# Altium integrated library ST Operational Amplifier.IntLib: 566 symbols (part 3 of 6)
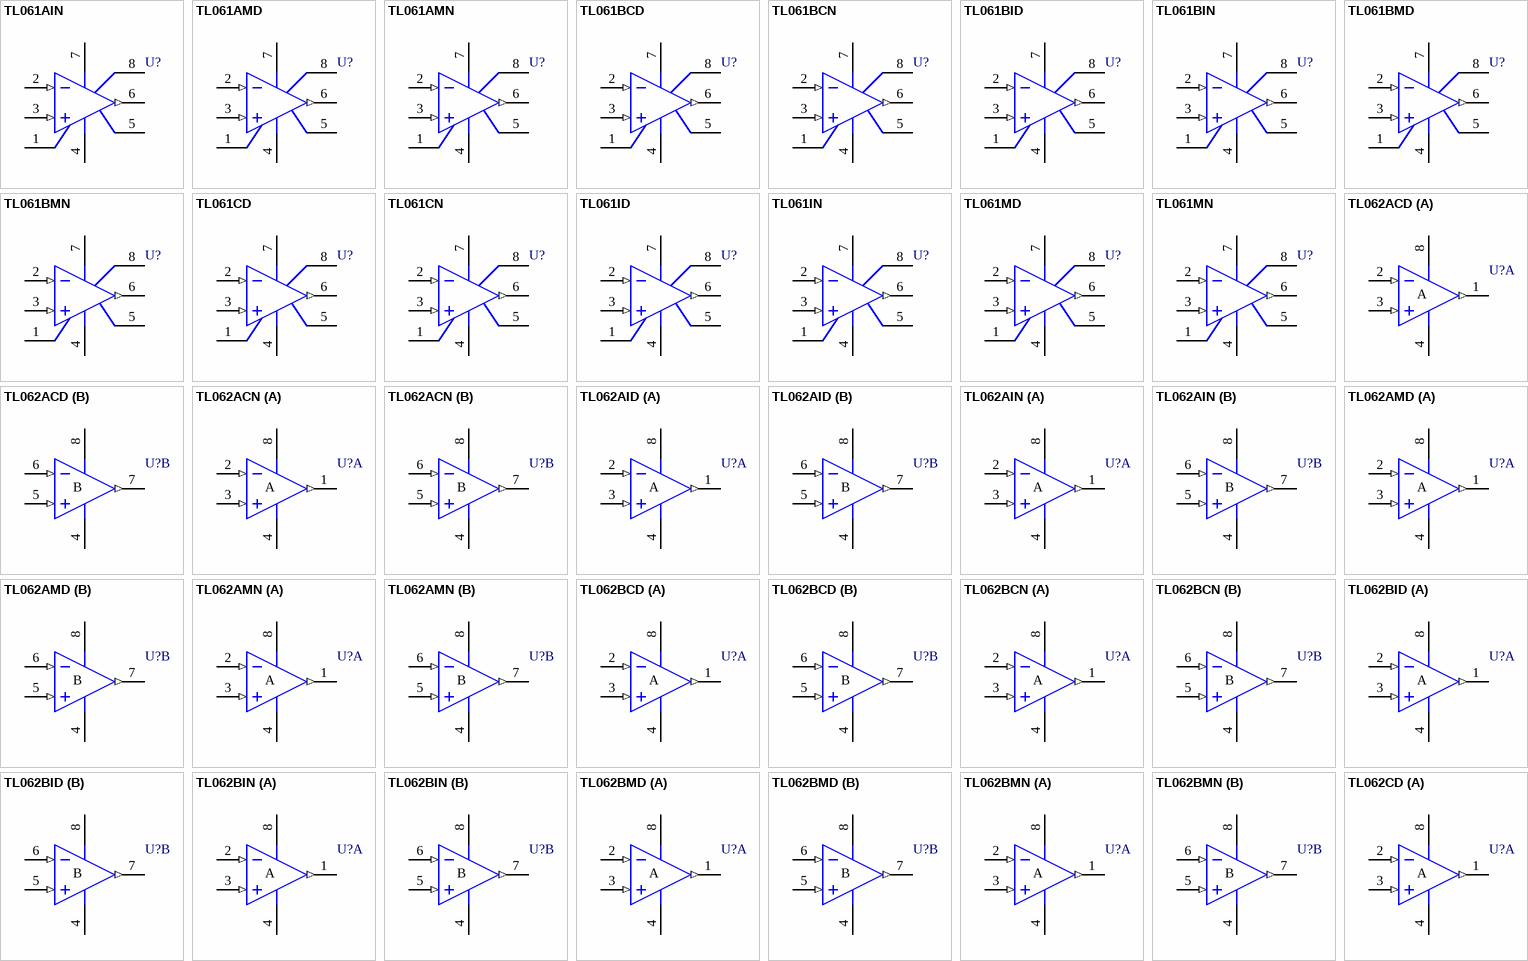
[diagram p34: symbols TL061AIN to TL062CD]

## TL061AMD
designator U?
Low-Power J-FET Single Operational Amplifier
footprint SO8_N (SOIC, 8-Leads, Body 4.9x3.9mm, Pitch 1.27mm, IPC Medium Density)
footprint SO8_L (SOIC, 8-Leads, Body 4.9x3.9mm, Pitch 1.27mm, IPC High Density)
footprint SO8_M (SOIC, 8-Leads, Body 4.9x3.9mm, Pitch 1.27mm, IPC Low Density)
3D model SO8 (8-Pin Small Outline Integrated Circuit 1.27 mm Pitch)
simulation model TL061 (SUBCKT)
pins: 1 OS NULL, 2 IN- (in), 3 IN+ (in), 4 V- (power), 5 OS NULL, 6 OUT (out), 7 V+ (power), 8 NC

## TL061AMN
designator U?
Low-Power J-FET Single Operational Amplifier
footprint DIP8 (DIP; 8 Leads; Row Spacing 7.62 mm; Pitch 2.54 mm)
3D model DIP8 (DIP; 8 Leads; Row Spacing 7.62 mm; Pitch 2.54 mm)
simulation model TL061 (SUBCKT)
pins: 1 OS NULL, 2 IN- (in), 3 IN+ (in), 4 V- (power), 5 OS NULL, 6 OUT (out), 7 V+ (power), 8 NC

## TL061BCD
designator U?
Low-Power J-FET Single Operational Amplifier
footprint SO8_N (SOIC, 8-Leads, Body 4.9x3.9mm, Pitch 1.27mm, IPC Medium Density)
footprint SO8_L (SOIC, 8-Leads, Body 4.9x3.9mm, Pitch 1.27mm, IPC High Density)
footprint SO8_M (SOIC, 8-Leads, Body 4.9x3.9mm, Pitch 1.27mm, IPC Low Density)
3D model SO8 (8-Pin Small Outline Integrated Circuit 1.27 mm Pitch)
simulation model TL061 (SUBCKT)
pins: 1 OS NULL, 2 IN- (in), 3 IN+ (in), 4 V- (power), 5 OS NULL, 6 OUT (out), 7 V+ (power), 8 NC

## TL061BCN
designator U?
Low-Power J-FET Single Operational Amplifier
footprint DIP8 (DIP; 8 Leads; Row Spacing 7.62 mm; Pitch 2.54 mm)
3D model DIP8 (DIP; 8 Leads; Row Spacing 7.62 mm; Pitch 2.54 mm)
simulation model TL061 (SUBCKT)
pins: 1 OS NULL, 2 IN- (in), 3 IN+ (in), 4 V- (power), 5 OS NULL, 6 OUT (out), 7 V+ (power), 8 NC

## TL061BID
designator U?
Low-Power J-FET Single Operational Amplifier
footprint SO8_N (SOIC, 8-Leads, Body 4.9x3.9mm, Pitch 1.27mm, IPC Medium Density)
footprint SO8_L (SOIC, 8-Leads, Body 4.9x3.9mm, Pitch 1.27mm, IPC High Density)
footprint SO8_M (SOIC, 8-Leads, Body 4.9x3.9mm, Pitch 1.27mm, IPC Low Density)
3D model SO8 (8-Pin Small Outline Integrated Circuit 1.27 mm Pitch)
simulation model TL061 (SUBCKT)
pins: 1 OS NULL, 2 IN- (in), 3 IN+ (in), 4 V- (power), 5 OS NULL, 6 OUT (out), 7 V+ (power), 8 NC

## TL061BIN
designator U?
Low-Power J-FET Single Operational Amplifier
footprint DIP8 (DIP; 8 Leads; Row Spacing 7.62 mm; Pitch 2.54 mm)
3D model DIP8 (DIP; 8 Leads; Row Spacing 7.62 mm; Pitch 2.54 mm)
simulation model TL061 (SUBCKT)
pins: 1 OS NULL, 2 IN- (in), 3 IN+ (in), 4 V- (power), 5 OS NULL, 6 OUT (out), 7 V+ (power), 8 NC

## TL061BMD
designator U?
Low-Power J-FET Single Operational Amplifier
footprint SO8_N (SOIC, 8-Leads, Body 4.9x3.9mm, Pitch 1.27mm, IPC Medium Density)
footprint SO8_L (SOIC, 8-Leads, Body 4.9x3.9mm, Pitch 1.27mm, IPC High Density)
footprint SO8_M (SOIC, 8-Leads, Body 4.9x3.9mm, Pitch 1.27mm, IPC Low Density)
3D model SO8 (8-Pin Small Outline Integrated Circuit 1.27 mm Pitch)
simulation model TL061 (SUBCKT)
pins: 1 OS NULL, 2 IN- (in), 3 IN+ (in), 4 V- (power), 5 OS NULL, 6 OUT (out), 7 V+ (power), 8 NC

## TL061BMN
designator U?
Low-Power J-FET Single Operational Amplifier
footprint DIP8 (DIP; 8 Leads; Row Spacing 7.62 mm; Pitch 2.54 mm)
3D model DIP8 (DIP; 8 Leads; Row Spacing 7.62 mm; Pitch 2.54 mm)
simulation model TL061 (SUBCKT)
pins: 1 OS NULL, 2 IN- (in), 3 IN+ (in), 4 V- (power), 5 OS NULL, 6 OUT (out), 7 V+ (power), 8 NC

## TL061CD
designator U?
Low-Power J-FET Single Operational Amplifier
footprint SO8_N (SOIC, 8-Leads, Body 4.9x3.9mm, Pitch 1.27mm, IPC Medium Density)
footprint SO8_L (SOIC, 8-Leads, Body 4.9x3.9mm, Pitch 1.27mm, IPC High Density)
footprint SO8_M (SOIC, 8-Leads, Body 4.9x3.9mm, Pitch 1.27mm, IPC Low Density)
3D model SO8 (8-Pin Small Outline Integrated Circuit 1.27 mm Pitch)
simulation model TL061 (SUBCKT)
pins: 1 OS NULL, 2 IN- (in), 3 IN+ (in), 4 V- (power), 5 OS NULL, 6 OUT (out), 7 V+ (power), 8 NC

## TL061CN
designator U?
Low-Power J-FET Single Operational Amplifier
footprint DIP8 (DIP; 8 Leads; Row Spacing 7.62 mm; Pitch 2.54 mm)
3D model DIP8 (DIP; 8 Leads; Row Spacing 7.62 mm; Pitch 2.54 mm)
simulation model TL061 (SUBCKT)
pins: 1 OS NULL, 2 IN- (in), 3 IN+ (in), 4 V- (power), 5 OS NULL, 6 OUT (out), 7 V+ (power), 8 NC

## TL061ID
designator U?
Low-Power J-FET Single Operational Amplifier
footprint SO8_N (SOIC, 8-Leads, Body 4.9x3.9mm, Pitch 1.27mm, IPC Medium Density)
footprint SO8_L (SOIC, 8-Leads, Body 4.9x3.9mm, Pitch 1.27mm, IPC High Density)
footprint SO8_M (SOIC, 8-Leads, Body 4.9x3.9mm, Pitch 1.27mm, IPC Low Density)
3D model SO8 (8-Pin Small Outline Integrated Circuit 1.27 mm Pitch)
simulation model TL061 (SUBCKT)
pins: 1 OS NULL, 2 IN- (in), 3 IN+ (in), 4 V- (power), 5 OS NULL, 6 OUT (out), 7 V+ (power), 8 NC

## TL061IN
designator U?
Low-Power J-FET Single Operational Amplifier
footprint DIP8 (DIP; 8 Leads; Row Spacing 7.62 mm; Pitch 2.54 mm)
3D model DIP8 (DIP; 8 Leads; Row Spacing 7.62 mm; Pitch 2.54 mm)
simulation model TL061 (SUBCKT)
pins: 1 OS NULL, 2 IN- (in), 3 IN+ (in), 4 V- (power), 5 OS NULL, 6 OUT (out), 7 V+ (power), 8 NC

## TL061MD
designator U?
Low-Power J-FET Single Operational Amplifier
footprint SO8_N (SOIC, 8-Leads, Body 4.9x3.9mm, Pitch 1.27mm, IPC Medium Density)
footprint SO8_L (SOIC, 8-Leads, Body 4.9x3.9mm, Pitch 1.27mm, IPC High Density)
footprint SO8_M (SOIC, 8-Leads, Body 4.9x3.9mm, Pitch 1.27mm, IPC Low Density)
3D model SO8 (8-Pin Small Outline Integrated Circuit 1.27 mm Pitch)
simulation model TL061 (SUBCKT)
pins: 1 OS NULL, 2 IN- (in), 3 IN+ (in), 4 V- (power), 5 OS NULL, 6 OUT (out), 7 V+ (power), 8 NC

## TL061MN
designator U?
Low-Power J-FET Single Operational Amplifier
footprint DIP8 (DIP; 8 Leads; Row Spacing 7.62 mm; Pitch 2.54 mm)
3D model DIP8 (DIP; 8 Leads; Row Spacing 7.62 mm; Pitch 2.54 mm)
simulation model TL061 (SUBCKT)
pins: 1 OS NULL, 2 IN- (in), 3 IN+ (in), 4 V- (power), 5 OS NULL, 6 OUT (out), 7 V+ (power), 8 NC

## TL062ACD
designator U?
Low-Power J-FET Dual Bipolar Operational Amplifier
footprint SO8_N (SOIC, 8-Leads, Body 4.9x3.9mm, Pitch 1.27mm, IPC Medium Density)
footprint SO8_L (SOIC, 8-Leads, Body 4.9x3.9mm, Pitch 1.27mm, IPC High Density)
footprint SO8_M (SOIC, 8-Leads, Body 4.9x3.9mm, Pitch 1.27mm, IPC Low Density)
3D model SO8 (8-Pin Small Outline Integrated Circuit 1.27 mm Pitch)
simulation model TL062 (SUBCKT)
pins on every part: 4 V- (power), 8 V+ (power)
part A pins: 1 OUT (out), 2 IN- (in), 3 IN+ (in)
part B pins: 5 IN+ (in), 6 IN- (in), 7 OUT (out)

## TL062ACN
designator U?
Low-Power J-FET Dual Bipolar Operational Amplifier
footprint DIP8 (DIP; 8 Leads; Row Spacing 7.62 mm; Pitch 2.54 mm)
3D model DIP8 (DIP; 8 Leads; Row Spacing 7.62 mm; Pitch 2.54 mm)
simulation model TL062 (SUBCKT)
pins on every part: 4 V- (power), 8 V+ (power)
part A pins: 1 OUT (out), 2 IN- (in), 3 IN+ (in)
part B pins: 5 IN+ (in), 6 IN- (in), 7 OUT (out)

## TL062AID
designator U?
Low-Power J-FET Dual Bipolar Operational Amplifier
footprint SO8_N (SOIC, 8-Leads, Body 4.9x3.9mm, Pitch 1.27mm, IPC Medium Density)
footprint SO8_L (SOIC, 8-Leads, Body 4.9x3.9mm, Pitch 1.27mm, IPC High Density)
footprint SO8_M (SOIC, 8-Leads, Body 4.9x3.9mm, Pitch 1.27mm, IPC Low Density)
3D model SO8 (8-Pin Small Outline Integrated Circuit 1.27 mm Pitch)
simulation model TL062 (SUBCKT)
pins on every part: 4 V- (power), 8 V+ (power)
part A pins: 1 OUT (out), 2 IN- (in), 3 IN+ (in)
part B pins: 5 IN+ (in), 6 IN- (in), 7 OUT (out)

## TL062AIN
designator U?
Low-Power J-FET Dual Bipolar Operational Amplifier
footprint DIP8 (DIP; 8 Leads; Row Spacing 7.62 mm; Pitch 2.54 mm)
3D model DIP8 (DIP; 8 Leads; Row Spacing 7.62 mm; Pitch 2.54 mm)
simulation model TL062 (SUBCKT)
pins on every part: 4 V- (power), 8 V+ (power)
part A pins: 1 OUT (out), 2 IN- (in), 3 IN+ (in)
part B pins: 5 IN+ (in), 6 IN- (in), 7 OUT (out)

## TL062AMD
designator U?
Low-Power J-FET Dual Bipolar Operational Amplifier
footprint SO8_N (SOIC, 8-Leads, Body 4.9x3.9mm, Pitch 1.27mm, IPC Medium Density)
footprint SO8_L (SOIC, 8-Leads, Body 4.9x3.9mm, Pitch 1.27mm, IPC High Density)
footprint SO8_M (SOIC, 8-Leads, Body 4.9x3.9mm, Pitch 1.27mm, IPC Low Density)
3D model SO8 (8-Pin Small Outline Integrated Circuit 1.27 mm Pitch)
simulation model TL062 (SUBCKT)
pins on every part: 4 V- (power), 8 V+ (power)
part A pins: 1 OUT (out), 2 IN- (in), 3 IN+ (in)
part B pins: 5 IN+ (in), 6 IN- (in), 7 OUT (out)

## TL062AMN
designator U?
Low-Power J-FET Dual Bipolar Operational Amplifier
footprint DIP8 (DIP; 8 Leads; Row Spacing 7.62 mm; Pitch 2.54 mm)
3D model DIP8 (DIP; 8 Leads; Row Spacing 7.62 mm; Pitch 2.54 mm)
simulation model TL062 (SUBCKT)
pins on every part: 4 V- (power), 8 V+ (power)
part A pins: 1 OUT (out), 2 IN- (in), 3 IN+ (in)
part B pins: 5 IN+ (in), 6 IN- (in), 7 OUT (out)

## TL062BCD
designator U?
Low-Power J-FET Dual Bipolar Operational Amplifier
footprint SO8_N (SOIC, 8-Leads, Body 4.9x3.9mm, Pitch 1.27mm, IPC Medium Density)
footprint SO8_L (SOIC, 8-Leads, Body 4.9x3.9mm, Pitch 1.27mm, IPC High Density)
footprint SO8_M (SOIC, 8-Leads, Body 4.9x3.9mm, Pitch 1.27mm, IPC Low Density)
3D model SO8 (8-Pin Small Outline Integrated Circuit 1.27 mm Pitch)
simulation model TL062 (SUBCKT)
pins on every part: 4 V- (power), 8 V+ (power)
part A pins: 1 OUT (out), 2 IN- (in), 3 IN+ (in)
part B pins: 5 IN+ (in), 6 IN- (in), 7 OUT (out)

## TL062BCN
designator U?
Low-Power J-FET Dual Bipolar Operational Amplifier
footprint DIP8 (DIP; 8 Leads; Row Spacing 7.62 mm; Pitch 2.54 mm)
3D model DIP8 (DIP; 8 Leads; Row Spacing 7.62 mm; Pitch 2.54 mm)
simulation model TL062 (SUBCKT)
pins on every part: 4 V- (power), 8 V+ (power)
part A pins: 1 OUT (out), 2 IN- (in), 3 IN+ (in)
part B pins: 5 IN+ (in), 6 IN- (in), 7 OUT (out)

## TL062BID
designator U?
Low-Power J-FET Dual Bipolar Operational Amplifier
footprint SO8_N (SOIC, 8-Leads, Body 4.9x3.9mm, Pitch 1.27mm, IPC Medium Density)
footprint SO8_L (SOIC, 8-Leads, Body 4.9x3.9mm, Pitch 1.27mm, IPC High Density)
footprint SO8_M (SOIC, 8-Leads, Body 4.9x3.9mm, Pitch 1.27mm, IPC Low Density)
3D model SO8 (8-Pin Small Outline Integrated Circuit 1.27 mm Pitch)
simulation model TL062 (SUBCKT)
pins on every part: 4 V- (power), 8 V+ (power)
part A pins: 1 OUT (out), 2 IN- (in), 3 IN+ (in)
part B pins: 5 IN+ (in), 6 IN- (in), 7 OUT (out)

## TL062BIN
designator U?
Low-Power J-FET Dual Bipolar Operational Amplifier
footprint DIP8 (DIP; 8 Leads; Row Spacing 7.62 mm; Pitch 2.54 mm)
3D model DIP8 (DIP; 8 Leads; Row Spacing 7.62 mm; Pitch 2.54 mm)
simulation model TL062 (SUBCKT)
pins on every part: 4 V- (power), 8 V+ (power)
part A pins: 1 OUT (out), 2 IN- (in), 3 IN+ (in)
part B pins: 5 IN+ (in), 6 IN- (in), 7 OUT (out)

## TL062BMD
designator U?
Low-Power J-FET Dual Bipolar Operational Amplifier
footprint SO8_N (SOIC, 8-Leads, Body 4.9x3.9mm, Pitch 1.27mm, IPC Medium Density)
footprint SO8_L (SOIC, 8-Leads, Body 4.9x3.9mm, Pitch 1.27mm, IPC High Density)
footprint SO8_M (SOIC, 8-Leads, Body 4.9x3.9mm, Pitch 1.27mm, IPC Low Density)
3D model SO8 (8-Pin Small Outline Integrated Circuit 1.27 mm Pitch)
simulation model TL062 (SUBCKT)
pins on every part: 4 V- (power), 8 V+ (power)
part A pins: 1 OUT (out), 2 IN- (in), 3 IN+ (in)
part B pins: 5 IN+ (in), 6 IN- (in), 7 OUT (out)

## TL062BMN
designator U?
Low-Power J-FET Dual Bipolar Operational Amplifier
footprint DIP8 (DIP; 8 Leads; Row Spacing 7.62 mm; Pitch 2.54 mm)
3D model DIP8 (DIP; 8 Leads; Row Spacing 7.62 mm; Pitch 2.54 mm)
simulation model TL062 (SUBCKT)
pins on every part: 4 V- (power), 8 V+ (power)
part A pins: 1 OUT (out), 2 IN- (in), 3 IN+ (in)
part B pins: 5 IN+ (in), 6 IN- (in), 7 OUT (out)

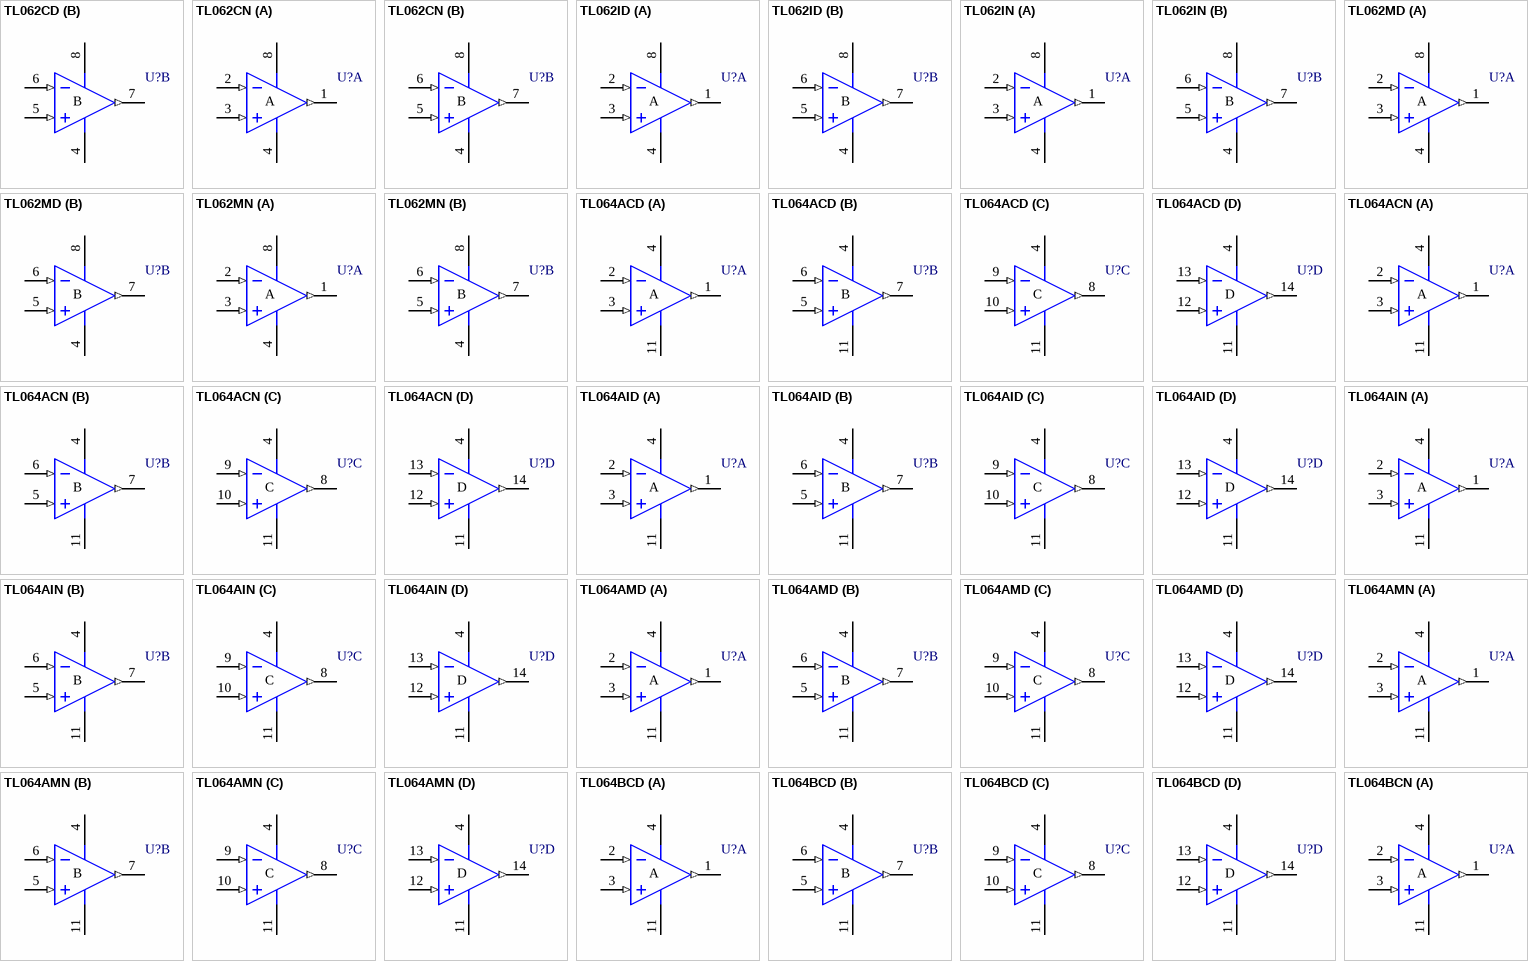
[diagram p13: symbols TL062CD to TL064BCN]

## TL062CD
designator U?
Low-Power J-FET Dual Bipolar Operational Amplifier
footprint SO8_N (SOIC, 8-Leads, Body 4.9x3.9mm, Pitch 1.27mm, IPC Medium Density)
footprint SO8_L (SOIC, 8-Leads, Body 4.9x3.9mm, Pitch 1.27mm, IPC High Density)
footprint SO8_M (SOIC, 8-Leads, Body 4.9x3.9mm, Pitch 1.27mm, IPC Low Density)
3D model SO8 (8-Pin Small Outline Integrated Circuit 1.27 mm Pitch)
simulation model TL062 (SUBCKT)
pins on every part: 4 V- (power), 8 V+ (power)
part A pins: 1 OUT (out), 2 IN- (in), 3 IN+ (in)
part B pins: 5 IN+ (in), 6 IN- (in), 7 OUT (out)

## TL062CN
designator U?
Low-Power J-FET Dual Bipolar Operational Amplifier
footprint DIP8 (DIP; 8 Leads; Row Spacing 7.62 mm; Pitch 2.54 mm)
3D model DIP8 (DIP; 8 Leads; Row Spacing 7.62 mm; Pitch 2.54 mm)
simulation model TL062 (SUBCKT)
pins on every part: 4 V- (power), 8 V+ (power)
part A pins: 1 OUT (out), 2 IN- (in), 3 IN+ (in)
part B pins: 5 IN+ (in), 6 IN- (in), 7 OUT (out)

## TL062ID
designator U?
Low-Power J-FET Dual Bipolar Operational Amplifier
footprint SO8_N (SOIC, 8-Leads, Body 4.9x3.9mm, Pitch 1.27mm, IPC Medium Density)
footprint SO8_L (SOIC, 8-Leads, Body 4.9x3.9mm, Pitch 1.27mm, IPC High Density)
footprint SO8_M (SOIC, 8-Leads, Body 4.9x3.9mm, Pitch 1.27mm, IPC Low Density)
3D model SO8 (8-Pin Small Outline Integrated Circuit 1.27 mm Pitch)
simulation model TL062 (SUBCKT)
pins on every part: 4 V- (power), 8 V+ (power)
part A pins: 1 OUT (out), 2 IN- (in), 3 IN+ (in)
part B pins: 5 IN+ (in), 6 IN- (in), 7 OUT (out)

## TL062IN
designator U?
Low-Power J-FET Dual Bipolar Operational Amplifier
footprint DIP8 (DIP; 8 Leads; Row Spacing 7.62 mm; Pitch 2.54 mm)
3D model DIP8 (DIP; 8 Leads; Row Spacing 7.62 mm; Pitch 2.54 mm)
simulation model TL062 (SUBCKT)
pins on every part: 4 V- (power), 8 V+ (power)
part A pins: 1 OUT (out), 2 IN- (in), 3 IN+ (in)
part B pins: 5 IN+ (in), 6 IN- (in), 7 OUT (out)

## TL062MD
designator U?
Low-Power J-FET Dual Bipolar Operational Amplifier
footprint SO8_N (SOIC, 8-Leads, Body 4.9x3.9mm, Pitch 1.27mm, IPC Medium Density)
footprint SO8_L (SOIC, 8-Leads, Body 4.9x3.9mm, Pitch 1.27mm, IPC High Density)
footprint SO8_M (SOIC, 8-Leads, Body 4.9x3.9mm, Pitch 1.27mm, IPC Low Density)
3D model SO8 (8-Pin Small Outline Integrated Circuit 1.27 mm Pitch)
simulation model TL062 (SUBCKT)
pins on every part: 4 V- (power), 8 V+ (power)
part A pins: 1 OUT (out), 2 IN- (in), 3 IN+ (in)
part B pins: 5 IN+ (in), 6 IN- (in), 7 OUT (out)

## TL062MN
designator U?
Low-Power J-FET Dual Bipolar Operational Amplifier
footprint DIP8 (DIP; 8 Leads; Row Spacing 7.62 mm; Pitch 2.54 mm)
3D model DIP8 (DIP; 8 Leads; Row Spacing 7.62 mm; Pitch 2.54 mm)
simulation model TL062 (SUBCKT)
pins on every part: 4 V- (power), 8 V+ (power)
part A pins: 1 OUT (out), 2 IN- (in), 3 IN+ (in)
part B pins: 5 IN+ (in), 6 IN- (in), 7 OUT (out)

## TL064ACD
designator U?
Low-Power J-FET Quad Operational Amplifier
footprint SO14_N (SOIC, 14-Leads, Body 8.7x3.9mm, Pitch 1.27mm, IPC Medium Density)
footprint SO14_L (SOIC, 14-Leads, Body 8.7x3.9mm, Pitch 1.27mm, IPC High Density)
footprint SO14_M (SOIC, 14-Leads, Body 8.7x3.9mm, Pitch 1.27mm, IPC Low Density)
3D model SO14 (14-Pin Small Outline Integrated Circuit 1.27 mm Pitch)
simulation model TL064 (SUBCKT)
pins on every part: 4 V+ (power), 11 V- (power)
part A pins: 1 OUT (out), 2 IN- (in), 3 IN+ (in)
part B pins: 5 IN+ (in), 6 IN- (in), 7 OUT (out)
part C pins: 8 OUT (out), 9 IN- (in), 10 IN+ (in)
part D pins: 12 IN+ (in), 13 IN- (in), 14 OUT (out)

## TL064ACN
designator U?
Low-Power J-FET Quad Operational Amplifier
footprint DIP14 (DIP; 14 Leads; Row Spacing 7.62 mm; Pitch 2.54 mm)
3D model DIP14 (DIP; 14 Leads; Row Spacing 7.62 mm; Pitch 2.54 mm)
simulation model TL064 (SUBCKT)
pins on every part: 4 V+ (power), 11 V- (power)
part A pins: 1 OUT (out), 2 IN- (in), 3 IN+ (in)
part B pins: 5 IN+ (in), 6 IN- (in), 7 OUT (out)
part C pins: 8 OUT (out), 9 IN- (in), 10 IN+ (in)
part D pins: 12 IN+ (in), 13 IN- (in), 14 OUT (out)

## TL064AID
designator U?
Low-Power J-FET Quad Operational Amplifier
footprint SO14_N (SOIC, 14-Leads, Body 8.7x3.9mm, Pitch 1.27mm, IPC Medium Density)
footprint SO14_L (SOIC, 14-Leads, Body 8.7x3.9mm, Pitch 1.27mm, IPC High Density)
footprint SO14_M (SOIC, 14-Leads, Body 8.7x3.9mm, Pitch 1.27mm, IPC Low Density)
3D model SO14 (14-Pin Small Outline Integrated Circuit 1.27 mm Pitch)
simulation model TL064 (SUBCKT)
pins on every part: 4 V+ (power), 11 V- (power)
part A pins: 1 OUT (out), 2 IN- (in), 3 IN+ (in)
part B pins: 5 IN+ (in), 6 IN- (in), 7 OUT (out)
part C pins: 8 OUT (out), 9 IN- (in), 10 IN+ (in)
part D pins: 12 IN+ (in), 13 IN- (in), 14 OUT (out)

## TL064AIN
designator U?
Low-Power J-FET Quad Operational Amplifier
footprint DIP14 (DIP; 14 Leads; Row Spacing 7.62 mm; Pitch 2.54 mm)
3D model DIP14 (DIP; 14 Leads; Row Spacing 7.62 mm; Pitch 2.54 mm)
simulation model TL064 (SUBCKT)
pins on every part: 4 V+ (power), 11 V- (power)
part A pins: 1 OUT (out), 2 IN- (in), 3 IN+ (in)
part B pins: 5 IN+ (in), 6 IN- (in), 7 OUT (out)
part C pins: 8 OUT (out), 9 IN- (in), 10 IN+ (in)
part D pins: 12 IN+ (in), 13 IN- (in), 14 OUT (out)

## TL064AMD
designator U?
Low-Power J-FET Quad Operational Amplifier
footprint SO14_N (SOIC, 14-Leads, Body 8.7x3.9mm, Pitch 1.27mm, IPC Medium Density)
footprint SO14_L (SOIC, 14-Leads, Body 8.7x3.9mm, Pitch 1.27mm, IPC High Density)
footprint SO14_M (SOIC, 14-Leads, Body 8.7x3.9mm, Pitch 1.27mm, IPC Low Density)
3D model SO14 (14-Pin Small Outline Integrated Circuit 1.27 mm Pitch)
simulation model TL064 (SUBCKT)
pins on every part: 4 V+ (power), 11 V- (power)
part A pins: 1 OUT (out), 2 IN- (in), 3 IN+ (in)
part B pins: 5 IN+ (in), 6 IN- (in), 7 OUT (out)
part C pins: 8 OUT (out), 9 IN- (in), 10 IN+ (in)
part D pins: 12 IN+ (in), 13 IN- (in), 14 OUT (out)

## TL064AMN
designator U?
Low-Power J-FET Quad Operational Amplifier
footprint DIP14 (DIP; 14 Leads; Row Spacing 7.62 mm; Pitch 2.54 mm)
3D model DIP14 (DIP; 14 Leads; Row Spacing 7.62 mm; Pitch 2.54 mm)
simulation model TL064 (SUBCKT)
pins on every part: 4 V+ (power), 11 V- (power)
part A pins: 1 OUT (out), 2 IN- (in), 3 IN+ (in)
part B pins: 5 IN+ (in), 6 IN- (in), 7 OUT (out)
part C pins: 8 OUT (out), 9 IN- (in), 10 IN+ (in)
part D pins: 12 IN+ (in), 13 IN- (in), 14 OUT (out)

## TL064BCD
designator U?
Low-Power J-FET Quad Operational Amplifier
footprint SO14_N (SOIC, 14-Leads, Body 8.7x3.9mm, Pitch 1.27mm, IPC Medium Density)
footprint SO14_L (SOIC, 14-Leads, Body 8.7x3.9mm, Pitch 1.27mm, IPC High Density)
footprint SO14_M (SOIC, 14-Leads, Body 8.7x3.9mm, Pitch 1.27mm, IPC Low Density)
3D model SO14 (14-Pin Small Outline Integrated Circuit 1.27 mm Pitch)
simulation model TL064 (SUBCKT)
pins on every part: 4 V+ (power), 11 V- (power)
part A pins: 1 OUT (out), 2 IN- (in), 3 IN+ (in)
part B pins: 5 IN+ (in), 6 IN- (in), 7 OUT (out)
part C pins: 8 OUT (out), 9 IN- (in), 10 IN+ (in)
part D pins: 12 IN+ (in), 13 IN- (in), 14 OUT (out)

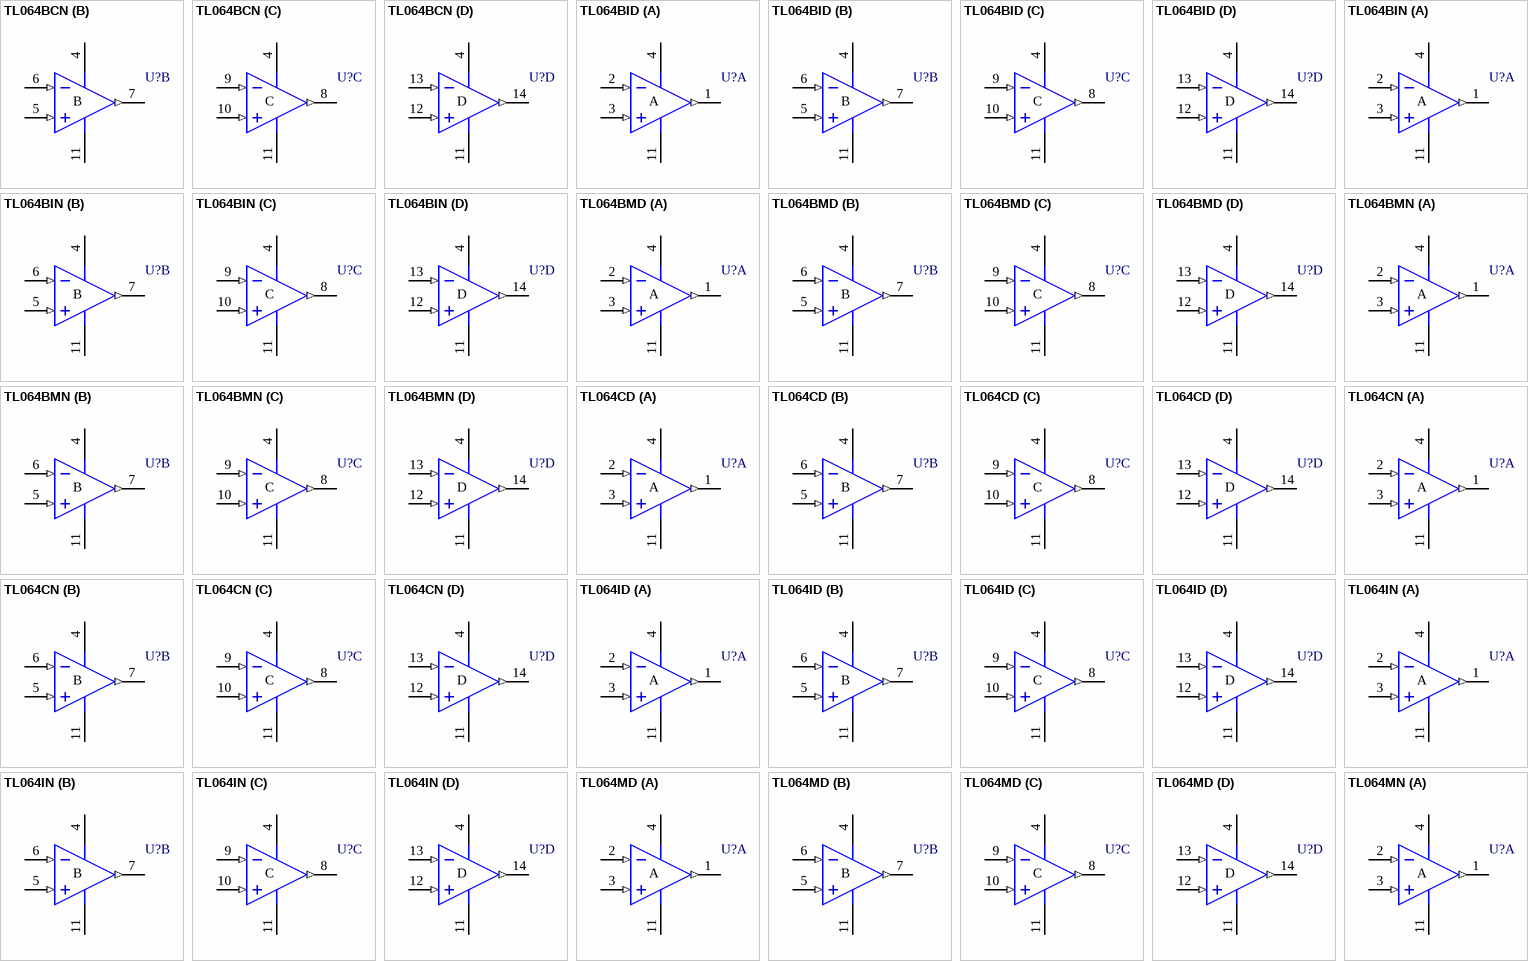
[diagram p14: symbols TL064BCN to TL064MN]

## TL064BCN
designator U?
Low-Power J-FET Quad Operational Amplifier
footprint DIP14 (DIP; 14 Leads; Row Spacing 7.62 mm; Pitch 2.54 mm)
3D model DIP14 (DIP; 14 Leads; Row Spacing 7.62 mm; Pitch 2.54 mm)
simulation model TL064 (SUBCKT)
pins on every part: 4 V+ (power), 11 V- (power)
part A pins: 1 OUT (out), 2 IN- (in), 3 IN+ (in)
part B pins: 5 IN+ (in), 6 IN- (in), 7 OUT (out)
part C pins: 8 OUT (out), 9 IN- (in), 10 IN+ (in)
part D pins: 12 IN+ (in), 13 IN- (in), 14 OUT (out)

## TL064BID
designator U?
Low-Power J-FET Quad Operational Amplifier
footprint SO14_N (SOIC, 14-Leads, Body 8.7x3.9mm, Pitch 1.27mm, IPC Medium Density)
footprint SO14_L (SOIC, 14-Leads, Body 8.7x3.9mm, Pitch 1.27mm, IPC High Density)
footprint SO14_M (SOIC, 14-Leads, Body 8.7x3.9mm, Pitch 1.27mm, IPC Low Density)
3D model SO14 (14-Pin Small Outline Integrated Circuit 1.27 mm Pitch)
simulation model TL064 (SUBCKT)
pins on every part: 4 V+ (power), 11 V- (power)
part A pins: 1 OUT (out), 2 IN- (in), 3 IN+ (in)
part B pins: 5 IN+ (in), 6 IN- (in), 7 OUT (out)
part C pins: 8 OUT (out), 9 IN- (in), 10 IN+ (in)
part D pins: 12 IN+ (in), 13 IN- (in), 14 OUT (out)

## TL064BIN
designator U?
Low-Power J-FET Quad Operational Amplifier
footprint DIP14 (DIP; 14 Leads; Row Spacing 7.62 mm; Pitch 2.54 mm)
3D model DIP14 (DIP; 14 Leads; Row Spacing 7.62 mm; Pitch 2.54 mm)
simulation model TL064 (SUBCKT)
pins on every part: 4 V+ (power), 11 V- (power)
part A pins: 1 OUT (out), 2 IN- (in), 3 IN+ (in)
part B pins: 5 IN+ (in), 6 IN- (in), 7 OUT (out)
part C pins: 8 OUT (out), 9 IN- (in), 10 IN+ (in)
part D pins: 12 IN+ (in), 13 IN- (in), 14 OUT (out)

## TL064BMD
designator U?
Low-Power J-FET Quad Operational Amplifier
footprint SO14_N (SOIC, 14-Leads, Body 8.7x3.9mm, Pitch 1.27mm, IPC Medium Density)
footprint SO14_L (SOIC, 14-Leads, Body 8.7x3.9mm, Pitch 1.27mm, IPC High Density)
footprint SO14_M (SOIC, 14-Leads, Body 8.7x3.9mm, Pitch 1.27mm, IPC Low Density)
3D model SO14 (14-Pin Small Outline Integrated Circuit 1.27 mm Pitch)
simulation model TL064 (SUBCKT)
pins on every part: 4 V+ (power), 11 V- (power)
part A pins: 1 OUT (out), 2 IN- (in), 3 IN+ (in)
part B pins: 5 IN+ (in), 6 IN- (in), 7 OUT (out)
part C pins: 8 OUT (out), 9 IN- (in), 10 IN+ (in)
part D pins: 12 IN+ (in), 13 IN- (in), 14 OUT (out)

## TL064BMN
designator U?
Low-Power J-FET Quad Operational Amplifier
footprint DIP14 (DIP; 14 Leads; Row Spacing 7.62 mm; Pitch 2.54 mm)
3D model DIP14 (DIP; 14 Leads; Row Spacing 7.62 mm; Pitch 2.54 mm)
simulation model TL064 (SUBCKT)
pins on every part: 4 V+ (power), 11 V- (power)
part A pins: 1 OUT (out), 2 IN- (in), 3 IN+ (in)
part B pins: 5 IN+ (in), 6 IN- (in), 7 OUT (out)
part C pins: 8 OUT (out), 9 IN- (in), 10 IN+ (in)
part D pins: 12 IN+ (in), 13 IN- (in), 14 OUT (out)

## TL064CD
designator U?
Low-Power J-FET Quad Operational Amplifier
footprint SO14_N (SOIC, 14-Leads, Body 8.7x3.9mm, Pitch 1.27mm, IPC Medium Density)
footprint SO14_L (SOIC, 14-Leads, Body 8.7x3.9mm, Pitch 1.27mm, IPC High Density)
footprint SO14_M (SOIC, 14-Leads, Body 8.7x3.9mm, Pitch 1.27mm, IPC Low Density)
3D model SO14 (14-Pin Small Outline Integrated Circuit 1.27 mm Pitch)
simulation model TL064 (SUBCKT)
pins on every part: 4 V+ (power), 11 V- (power)
part A pins: 1 OUT (out), 2 IN- (in), 3 IN+ (in)
part B pins: 5 IN+ (in), 6 IN- (in), 7 OUT (out)
part C pins: 8 OUT (out), 9 IN- (in), 10 IN+ (in)
part D pins: 12 IN+ (in), 13 IN- (in), 14 OUT (out)

## TL064CN
designator U?
Low-Power J-FET Quad Operational Amplifier
footprint DIP14 (DIP; 14 Leads; Row Spacing 7.62 mm; Pitch 2.54 mm)
3D model DIP14 (DIP; 14 Leads; Row Spacing 7.62 mm; Pitch 2.54 mm)
simulation model TL064 (SUBCKT)
pins on every part: 4 V+ (power), 11 V- (power)
part A pins: 1 OUT (out), 2 IN- (in), 3 IN+ (in)
part B pins: 5 IN+ (in), 6 IN- (in), 7 OUT (out)
part C pins: 8 OUT (out), 9 IN- (in), 10 IN+ (in)
part D pins: 12 IN+ (in), 13 IN- (in), 14 OUT (out)

## TL064ID
designator U?
Low-Power J-FET Quad Operational Amplifier
footprint SO14_N (SOIC, 14-Leads, Body 8.7x3.9mm, Pitch 1.27mm, IPC Medium Density)
footprint SO14_L (SOIC, 14-Leads, Body 8.7x3.9mm, Pitch 1.27mm, IPC High Density)
footprint SO14_M (SOIC, 14-Leads, Body 8.7x3.9mm, Pitch 1.27mm, IPC Low Density)
3D model SO14 (14-Pin Small Outline Integrated Circuit 1.27 mm Pitch)
simulation model TL064 (SUBCKT)
pins on every part: 4 V+ (power), 11 V- (power)
part A pins: 1 OUT (out), 2 IN- (in), 3 IN+ (in)
part B pins: 5 IN+ (in), 6 IN- (in), 7 OUT (out)
part C pins: 8 OUT (out), 9 IN- (in), 10 IN+ (in)
part D pins: 12 IN+ (in), 13 IN- (in), 14 OUT (out)

## TL064IN
designator U?
Low-Power J-FET Quad Operational Amplifier
footprint DIP14 (DIP; 14 Leads; Row Spacing 7.62 mm; Pitch 2.54 mm)
3D model DIP14 (DIP; 14 Leads; Row Spacing 7.62 mm; Pitch 2.54 mm)
simulation model TL064 (SUBCKT)
pins on every part: 4 V+ (power), 11 V- (power)
part A pins: 1 OUT (out), 2 IN- (in), 3 IN+ (in)
part B pins: 5 IN+ (in), 6 IN- (in), 7 OUT (out)
part C pins: 8 OUT (out), 9 IN- (in), 10 IN+ (in)
part D pins: 12 IN+ (in), 13 IN- (in), 14 OUT (out)

## TL064MD
designator U?
Low-Power J-FET Quad Operational Amplifier
footprint SO14_N (SOIC, 14-Leads, Body 8.7x3.9mm, Pitch 1.27mm, IPC Medium Density)
footprint SO14_L (SOIC, 14-Leads, Body 8.7x3.9mm, Pitch 1.27mm, IPC High Density)
footprint SO14_M (SOIC, 14-Leads, Body 8.7x3.9mm, Pitch 1.27mm, IPC Low Density)
3D model SO14 (14-Pin Small Outline Integrated Circuit 1.27 mm Pitch)
simulation model TL064 (SUBCKT)
pins on every part: 4 V+ (power), 11 V- (power)
part A pins: 1 OUT (out), 2 IN- (in), 3 IN+ (in)
part B pins: 5 IN+ (in), 6 IN- (in), 7 OUT (out)
part C pins: 8 OUT (out), 9 IN- (in), 10 IN+ (in)
part D pins: 12 IN+ (in), 13 IN- (in), 14 OUT (out)

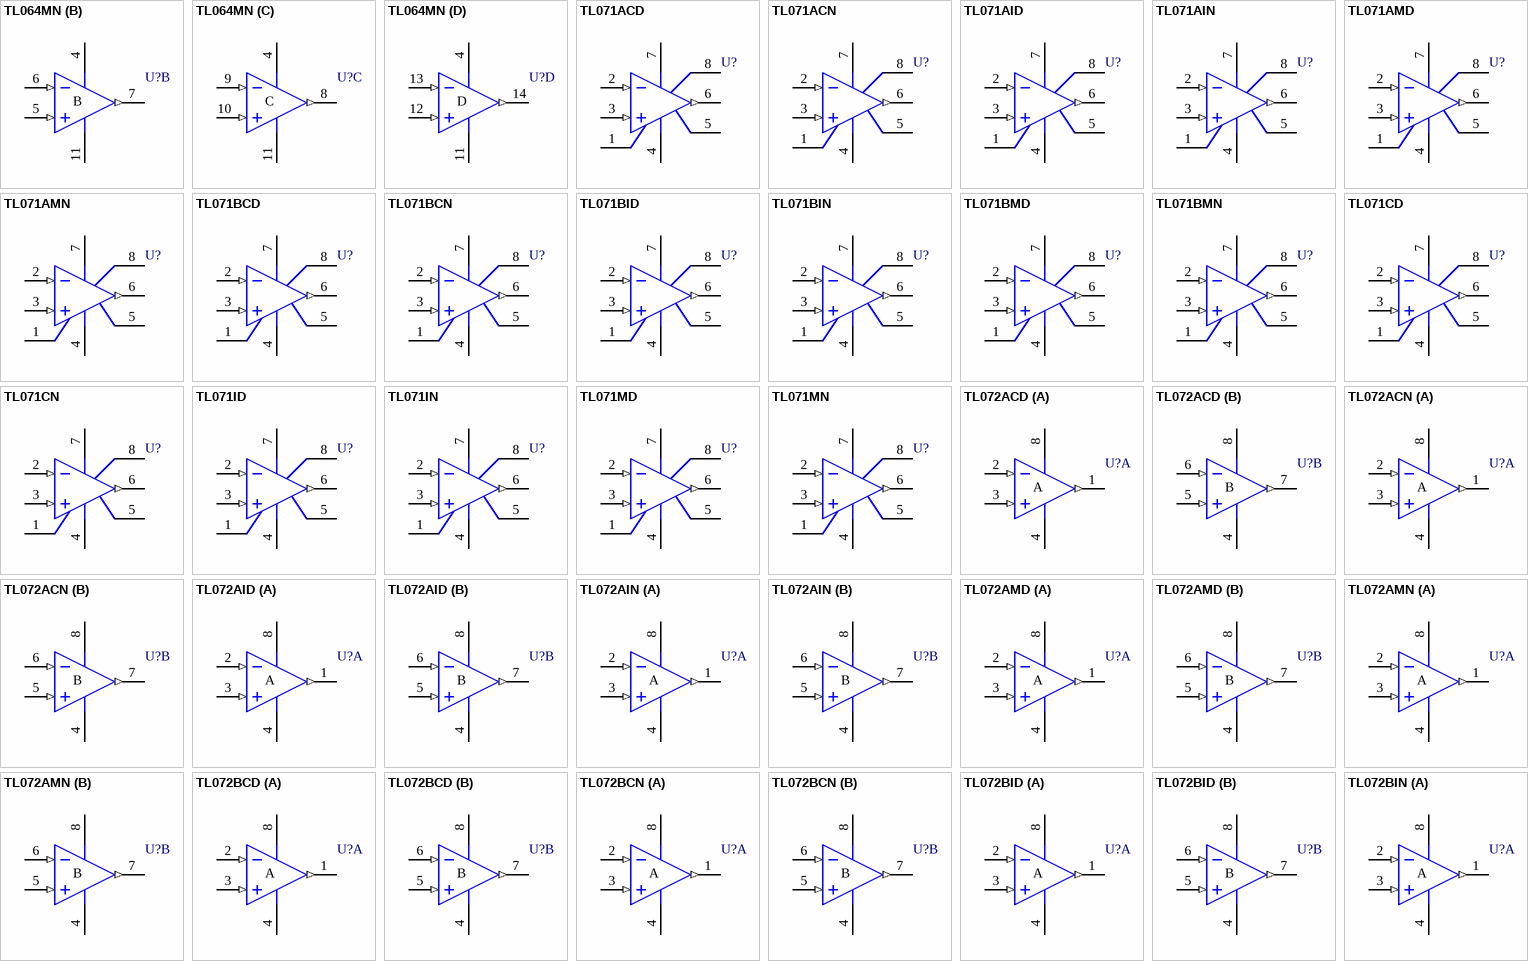
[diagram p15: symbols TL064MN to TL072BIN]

## TL064MN
designator U?
Low-Power J-FET Quad Operational Amplifier
footprint DIP14 (DIP; 14 Leads; Row Spacing 7.62 mm; Pitch 2.54 mm)
3D model DIP14 (DIP; 14 Leads; Row Spacing 7.62 mm; Pitch 2.54 mm)
simulation model TL064 (SUBCKT)
pins on every part: 4 V+ (power), 11 V- (power)
part A pins: 1 OUT (out), 2 IN- (in), 3 IN+ (in)
part B pins: 5 IN+ (in), 6 IN- (in), 7 OUT (out)
part C pins: 8 OUT (out), 9 IN- (in), 10 IN+ (in)
part D pins: 12 IN+ (in), 13 IN- (in), 14 OUT (out)

## TL071ACD
designator U?
Low-Noise J-FET Single Operational Amplifier
footprint SO8_N (SOIC, 8-Leads, Body 4.9x3.9mm, Pitch 1.27mm, IPC Medium Density)
footprint SO8_L (SOIC, 8-Leads, Body 4.9x3.9mm, Pitch 1.27mm, IPC High Density)
footprint SO8_M (SOIC, 8-Leads, Body 4.9x3.9mm, Pitch 1.27mm, IPC Low Density)
3D model SO8 (8-Pin Small Outline Integrated Circuit 1.27 mm Pitch)
simulation model TL071 (SUBCKT)
pins: 1 OS NULL, 2 IN- (in), 3 IN+ (in), 4 V- (power), 5 OS NULL, 6 OUT (out), 7 V+ (power), 8 NC

## TL071ACN
designator U?
Low-Noise J-FET Single Operational Amplifier
footprint DIP8 (DIP; 8 Leads; Row Spacing 7.62 mm; Pitch 2.54 mm)
3D model DIP8 (DIP; 8 Leads; Row Spacing 7.62 mm; Pitch 2.54 mm)
simulation model TL071 (SUBCKT)
pins: 1 OS NULL, 2 IN- (in), 3 IN+ (in), 4 V- (power), 5 OS NULL, 6 OUT (out), 7 V+ (power), 8 NC

## TL071AID
designator U?
Low-Noise J-FET Single Operational Amplifier
footprint SO8_N (SOIC, 8-Leads, Body 4.9x3.9mm, Pitch 1.27mm, IPC Medium Density)
footprint SO8_L (SOIC, 8-Leads, Body 4.9x3.9mm, Pitch 1.27mm, IPC High Density)
footprint SO8_M (SOIC, 8-Leads, Body 4.9x3.9mm, Pitch 1.27mm, IPC Low Density)
3D model SO8 (8-Pin Small Outline Integrated Circuit 1.27 mm Pitch)
simulation model TL071 (SUBCKT)
pins: 1 OS NULL, 2 IN- (in), 3 IN+ (in), 4 V- (power), 5 OS NULL, 6 OUT (out), 7 V+ (power), 8 NC

## TL071AIN
designator U?
Low-Noise J-FET Single Operational Amplifier
footprint DIP8 (DIP; 8 Leads; Row Spacing 7.62 mm; Pitch 2.54 mm)
3D model DIP8 (DIP; 8 Leads; Row Spacing 7.62 mm; Pitch 2.54 mm)
simulation model TL071 (SUBCKT)
pins: 1 OS NULL, 2 IN- (in), 3 IN+ (in), 4 V- (power), 5 OS NULL, 6 OUT (out), 7 V+ (power), 8 NC

## TL071AMD
designator U?
Low-Noise J-FET Single Operational Amplifier
footprint SO8_N (SOIC, 8-Leads, Body 4.9x3.9mm, Pitch 1.27mm, IPC Medium Density)
footprint SO8_L (SOIC, 8-Leads, Body 4.9x3.9mm, Pitch 1.27mm, IPC High Density)
footprint SO8_M (SOIC, 8-Leads, Body 4.9x3.9mm, Pitch 1.27mm, IPC Low Density)
3D model SO8 (8-Pin Small Outline Integrated Circuit 1.27 mm Pitch)
simulation model TL071 (SUBCKT)
pins: 1 OS NULL, 2 IN- (in), 3 IN+ (in), 4 V- (power), 5 OS NULL, 6 OUT (out), 7 V+ (power), 8 NC

## TL071AMN
designator U?
Low-Noise J-FET Single Operational Amplifier
footprint DIP8 (DIP; 8 Leads; Row Spacing 7.62 mm; Pitch 2.54 mm)
3D model DIP8 (DIP; 8 Leads; Row Spacing 7.62 mm; Pitch 2.54 mm)
simulation model TL071 (SUBCKT)
pins: 1 OS NULL, 2 IN- (in), 3 IN+ (in), 4 V- (power), 5 OS NULL, 6 OUT (out), 7 V+ (power), 8 NC

## TL071BCD
designator U?
Low-Noise J-FET Single Operational Amplifier
footprint SO8_N (SOIC, 8-Leads, Body 4.9x3.9mm, Pitch 1.27mm, IPC Medium Density)
footprint SO8_L (SOIC, 8-Leads, Body 4.9x3.9mm, Pitch 1.27mm, IPC High Density)
footprint SO8_M (SOIC, 8-Leads, Body 4.9x3.9mm, Pitch 1.27mm, IPC Low Density)
3D model SO8 (8-Pin Small Outline Integrated Circuit 1.27 mm Pitch)
simulation model TL071 (SUBCKT)
pins: 1 OS NULL, 2 IN- (in), 3 IN+ (in), 4 V- (power), 5 OS NULL, 6 OUT (out), 7 V+ (power), 8 NC

## TL071BCN
designator U?
Low-Noise J-FET Single Operational Amplifier
footprint DIP8 (DIP; 8 Leads; Row Spacing 7.62 mm; Pitch 2.54 mm)
3D model DIP8 (DIP; 8 Leads; Row Spacing 7.62 mm; Pitch 2.54 mm)
simulation model TL071 (SUBCKT)
pins: 1 OS NULL, 2 IN- (in), 3 IN+ (in), 4 V- (power), 5 OS NULL, 6 OUT (out), 7 V+ (power), 8 NC

## TL071BID
designator U?
Low-Noise J-FET Single Operational Amplifier
footprint SO8_N (SOIC, 8-Leads, Body 4.9x3.9mm, Pitch 1.27mm, IPC Medium Density)
footprint SO8_L (SOIC, 8-Leads, Body 4.9x3.9mm, Pitch 1.27mm, IPC High Density)
footprint SO8_M (SOIC, 8-Leads, Body 4.9x3.9mm, Pitch 1.27mm, IPC Low Density)
3D model SO8 (8-Pin Small Outline Integrated Circuit 1.27 mm Pitch)
simulation model TL071 (SUBCKT)
pins: 1 OS NULL, 2 IN- (in), 3 IN+ (in), 4 V- (power), 5 OS NULL, 6 OUT (out), 7 V+ (power), 8 NC

## TL071BIN
designator U?
Low-Noise J-FET Single Operational Amplifier
footprint DIP8 (DIP; 8 Leads; Row Spacing 7.62 mm; Pitch 2.54 mm)
3D model DIP8 (DIP; 8 Leads; Row Spacing 7.62 mm; Pitch 2.54 mm)
simulation model TL071 (SUBCKT)
pins: 1 OS NULL, 2 IN- (in), 3 IN+ (in), 4 V- (power), 5 OS NULL, 6 OUT (out), 7 V+ (power), 8 NC

## TL071BMD
designator U?
Low-Noise J-FET Single Operational Amplifier
footprint SO8_N (SOIC, 8-Leads, Body 4.9x3.9mm, Pitch 1.27mm, IPC Medium Density)
footprint SO8_L (SOIC, 8-Leads, Body 4.9x3.9mm, Pitch 1.27mm, IPC High Density)
footprint SO8_M (SOIC, 8-Leads, Body 4.9x3.9mm, Pitch 1.27mm, IPC Low Density)
3D model SO8 (8-Pin Small Outline Integrated Circuit 1.27 mm Pitch)
simulation model TL071 (SUBCKT)
pins: 1 OS NULL, 2 IN- (in), 3 IN+ (in), 4 V- (power), 5 OS NULL, 6 OUT (out), 7 V+ (power), 8 NC

## TL071BMN
designator U?
Low-Noise J-FET Single Operational Amplifier
footprint DIP8 (DIP; 8 Leads; Row Spacing 7.62 mm; Pitch 2.54 mm)
3D model DIP8 (DIP; 8 Leads; Row Spacing 7.62 mm; Pitch 2.54 mm)
simulation model TL071 (SUBCKT)
pins: 1 OS NULL, 2 IN- (in), 3 IN+ (in), 4 V- (power), 5 OS NULL, 6 OUT (out), 7 V+ (power), 8 NC

## TL071CD
designator U?
Low-Noise J-FET Single Operational Amplifier
footprint SO8_N (SOIC, 8-Leads, Body 4.9x3.9mm, Pitch 1.27mm, IPC Medium Density)
footprint SO8_L (SOIC, 8-Leads, Body 4.9x3.9mm, Pitch 1.27mm, IPC High Density)
footprint SO8_M (SOIC, 8-Leads, Body 4.9x3.9mm, Pitch 1.27mm, IPC Low Density)
3D model SO8 (8-Pin Small Outline Integrated Circuit 1.27 mm Pitch)
simulation model TL071 (SUBCKT)
pins: 1 OS NULL, 2 IN- (in), 3 IN+ (in), 4 V- (power), 5 OS NULL, 6 OUT (out), 7 V+ (power), 8 NC

## TL071CN
designator U?
Low-Noise J-FET Single Operational Amplifier
footprint DIP8 (DIP; 8 Leads; Row Spacing 7.62 mm; Pitch 2.54 mm)
3D model DIP8 (DIP; 8 Leads; Row Spacing 7.62 mm; Pitch 2.54 mm)
simulation model TL071 (SUBCKT)
pins: 1 OS NULL, 2 IN- (in), 3 IN+ (in), 4 V- (power), 5 OS NULL, 6 OUT (out), 7 V+ (power), 8 NC

## TL071ID
designator U?
Low-Noise J-FET Single Operational Amplifier
footprint SO8_N (SOIC, 8-Leads, Body 4.9x3.9mm, Pitch 1.27mm, IPC Medium Density)
footprint SO8_L (SOIC, 8-Leads, Body 4.9x3.9mm, Pitch 1.27mm, IPC High Density)
footprint SO8_M (SOIC, 8-Leads, Body 4.9x3.9mm, Pitch 1.27mm, IPC Low Density)
3D model SO8 (8-Pin Small Outline Integrated Circuit 1.27 mm Pitch)
simulation model TL071 (SUBCKT)
pins: 1 OS NULL, 2 IN- (in), 3 IN+ (in), 4 V- (power), 5 OS NULL, 6 OUT (out), 7 V+ (power), 8 NC

## TL071IN
designator U?
Low-Noise J-FET Single Operational Amplifier
footprint DIP8 (DIP; 8 Leads; Row Spacing 7.62 mm; Pitch 2.54 mm)
3D model DIP8 (DIP; 8 Leads; Row Spacing 7.62 mm; Pitch 2.54 mm)
simulation model TL071 (SUBCKT)
pins: 1 OS NULL, 2 IN- (in), 3 IN+ (in), 4 V- (power), 5 OS NULL, 6 OUT (out), 7 V+ (power), 8 NC

## TL071MD
designator U?
Low-Noise J-FET Single Operational Amplifier
footprint SO8_N (SOIC, 8-Leads, Body 4.9x3.9mm, Pitch 1.27mm, IPC Medium Density)
footprint SO8_L (SOIC, 8-Leads, Body 4.9x3.9mm, Pitch 1.27mm, IPC High Density)
footprint SO8_M (SOIC, 8-Leads, Body 4.9x3.9mm, Pitch 1.27mm, IPC Low Density)
3D model SO8 (8-Pin Small Outline Integrated Circuit 1.27 mm Pitch)
simulation model TL071 (SUBCKT)
pins: 1 OS NULL, 2 IN- (in), 3 IN+ (in), 4 V- (power), 5 OS NULL, 6 OUT (out), 7 V+ (power), 8 NC

## TL071MN
designator U?
Low-Noise J-FET Single Operational Amplifier
footprint DIP8 (DIP; 8 Leads; Row Spacing 7.62 mm; Pitch 2.54 mm)
3D model DIP8 (DIP; 8 Leads; Row Spacing 7.62 mm; Pitch 2.54 mm)
simulation model TL071 (SUBCKT)
pins: 1 OS NULL, 2 IN- (in), 3 IN+ (in), 4 V- (power), 5 OS NULL, 6 OUT (out), 7 V+ (power), 8 NC

## TL072ACD
designator U?
Low-Noise J-FET Dual Operational Amplifier
footprint SO8_N (SOIC, 8-Leads, Body 4.9x3.9mm, Pitch 1.27mm, IPC Medium Density)
footprint SO8_L (SOIC, 8-Leads, Body 4.9x3.9mm, Pitch 1.27mm, IPC High Density)
footprint SO8_M (SOIC, 8-Leads, Body 4.9x3.9mm, Pitch 1.27mm, IPC Low Density)
3D model SO8 (8-Pin Small Outline Integrated Circuit 1.27 mm Pitch)
simulation model TL072 (SUBCKT)
pins on every part: 4 V- (power), 8 V+ (power)
part A pins: 1 OUT (out), 2 IN- (in), 3 IN+ (in)
part B pins: 5 IN+ (in), 6 IN- (in), 7 OUT (out)

## TL072ACN
designator U?
Low-Noise J-FET Dual Operational Amplifier
footprint DIP8 (DIP; 8 Leads; Row Spacing 7.62 mm; Pitch 2.54 mm)
3D model DIP8 (DIP; 8 Leads; Row Spacing 7.62 mm; Pitch 2.54 mm)
simulation model TL072 (SUBCKT)
pins on every part: 4 V- (power), 8 V+ (power)
part A pins: 1 OUT (out), 2 IN- (in), 3 IN+ (in)
part B pins: 5 IN+ (in), 6 IN- (in), 7 OUT (out)

## TL072AID
designator U?
Low-Noise J-FET Dual Operational Amplifier
footprint SO8_N (SOIC, 8-Leads, Body 4.9x3.9mm, Pitch 1.27mm, IPC Medium Density)
footprint SO8_L (SOIC, 8-Leads, Body 4.9x3.9mm, Pitch 1.27mm, IPC High Density)
footprint SO8_M (SOIC, 8-Leads, Body 4.9x3.9mm, Pitch 1.27mm, IPC Low Density)
3D model SO8 (8-Pin Small Outline Integrated Circuit 1.27 mm Pitch)
simulation model TL072 (SUBCKT)
pins on every part: 4 V- (power), 8 V+ (power)
part A pins: 1 OUT (out), 2 IN- (in), 3 IN+ (in)
part B pins: 5 IN+ (in), 6 IN- (in), 7 OUT (out)

## TL072AIN
designator U?
Low-Noise J-FET Dual Operational Amplifier
footprint DIP8 (DIP; 8 Leads; Row Spacing 7.62 mm; Pitch 2.54 mm)
3D model DIP8 (DIP; 8 Leads; Row Spacing 7.62 mm; Pitch 2.54 mm)
simulation model TL072 (SUBCKT)
pins on every part: 4 V- (power), 8 V+ (power)
part A pins: 1 OUT (out), 2 IN- (in), 3 IN+ (in)
part B pins: 5 IN+ (in), 6 IN- (in), 7 OUT (out)

## TL072AMD
designator U?
Low-Noise J-FET Dual Operational Amplifier
footprint SO8_N (SOIC, 8-Leads, Body 4.9x3.9mm, Pitch 1.27mm, IPC Medium Density)
footprint SO8_L (SOIC, 8-Leads, Body 4.9x3.9mm, Pitch 1.27mm, IPC High Density)
footprint SO8_M (SOIC, 8-Leads, Body 4.9x3.9mm, Pitch 1.27mm, IPC Low Density)
3D model SO8 (8-Pin Small Outline Integrated Circuit 1.27 mm Pitch)
simulation model TL072 (SUBCKT)
pins on every part: 4 V- (power), 8 V+ (power)
part A pins: 1 OUT (out), 2 IN- (in), 3 IN+ (in)
part B pins: 5 IN+ (in), 6 IN- (in), 7 OUT (out)

## TL072AMN
designator U?
Low-Noise J-FET Dual Operational Amplifier
footprint DIP8 (DIP; 8 Leads; Row Spacing 7.62 mm; Pitch 2.54 mm)
3D model DIP8 (DIP; 8 Leads; Row Spacing 7.62 mm; Pitch 2.54 mm)
simulation model TL072 (SUBCKT)
pins on every part: 4 V- (power), 8 V+ (power)
part A pins: 1 OUT (out), 2 IN- (in), 3 IN+ (in)
part B pins: 5 IN+ (in), 6 IN- (in), 7 OUT (out)

## TL072BCD
designator U?
Low-Noise J-FET Dual Operational Amplifier
footprint SO8_N (SOIC, 8-Leads, Body 4.9x3.9mm, Pitch 1.27mm, IPC Medium Density)
footprint SO8_L (SOIC, 8-Leads, Body 4.9x3.9mm, Pitch 1.27mm, IPC High Density)
footprint SO8_M (SOIC, 8-Leads, Body 4.9x3.9mm, Pitch 1.27mm, IPC Low Density)
3D model SO8 (8-Pin Small Outline Integrated Circuit 1.27 mm Pitch)
simulation model TL072 (SUBCKT)
pins on every part: 4 V- (power), 8 V+ (power)
part A pins: 1 OUT (out), 2 IN- (in), 3 IN+ (in)
part B pins: 5 IN+ (in), 6 IN- (in), 7 OUT (out)

## TL072BCN
designator U?
Low-Noise J-FET Dual Operational Amplifier
footprint DIP8 (DIP; 8 Leads; Row Spacing 7.62 mm; Pitch 2.54 mm)
3D model DIP8 (DIP; 8 Leads; Row Spacing 7.62 mm; Pitch 2.54 mm)
simulation model TL072 (SUBCKT)
pins on every part: 4 V- (power), 8 V+ (power)
part A pins: 1 OUT (out), 2 IN- (in), 3 IN+ (in)
part B pins: 5 IN+ (in), 6 IN- (in), 7 OUT (out)

## TL072BID
designator U?
Low-Noise J-FET Dual Operational Amplifier
footprint SO8_N (SOIC, 8-Leads, Body 4.9x3.9mm, Pitch 1.27mm, IPC Medium Density)
footprint SO8_L (SOIC, 8-Leads, Body 4.9x3.9mm, Pitch 1.27mm, IPC High Density)
footprint SO8_M (SOIC, 8-Leads, Body 4.9x3.9mm, Pitch 1.27mm, IPC Low Density)
3D model SO8 (8-Pin Small Outline Integrated Circuit 1.27 mm Pitch)
simulation model TL072 (SUBCKT)
pins on every part: 4 V- (power), 8 V+ (power)
part A pins: 1 OUT (out), 2 IN- (in), 3 IN+ (in)
part B pins: 5 IN+ (in), 6 IN- (in), 7 OUT (out)

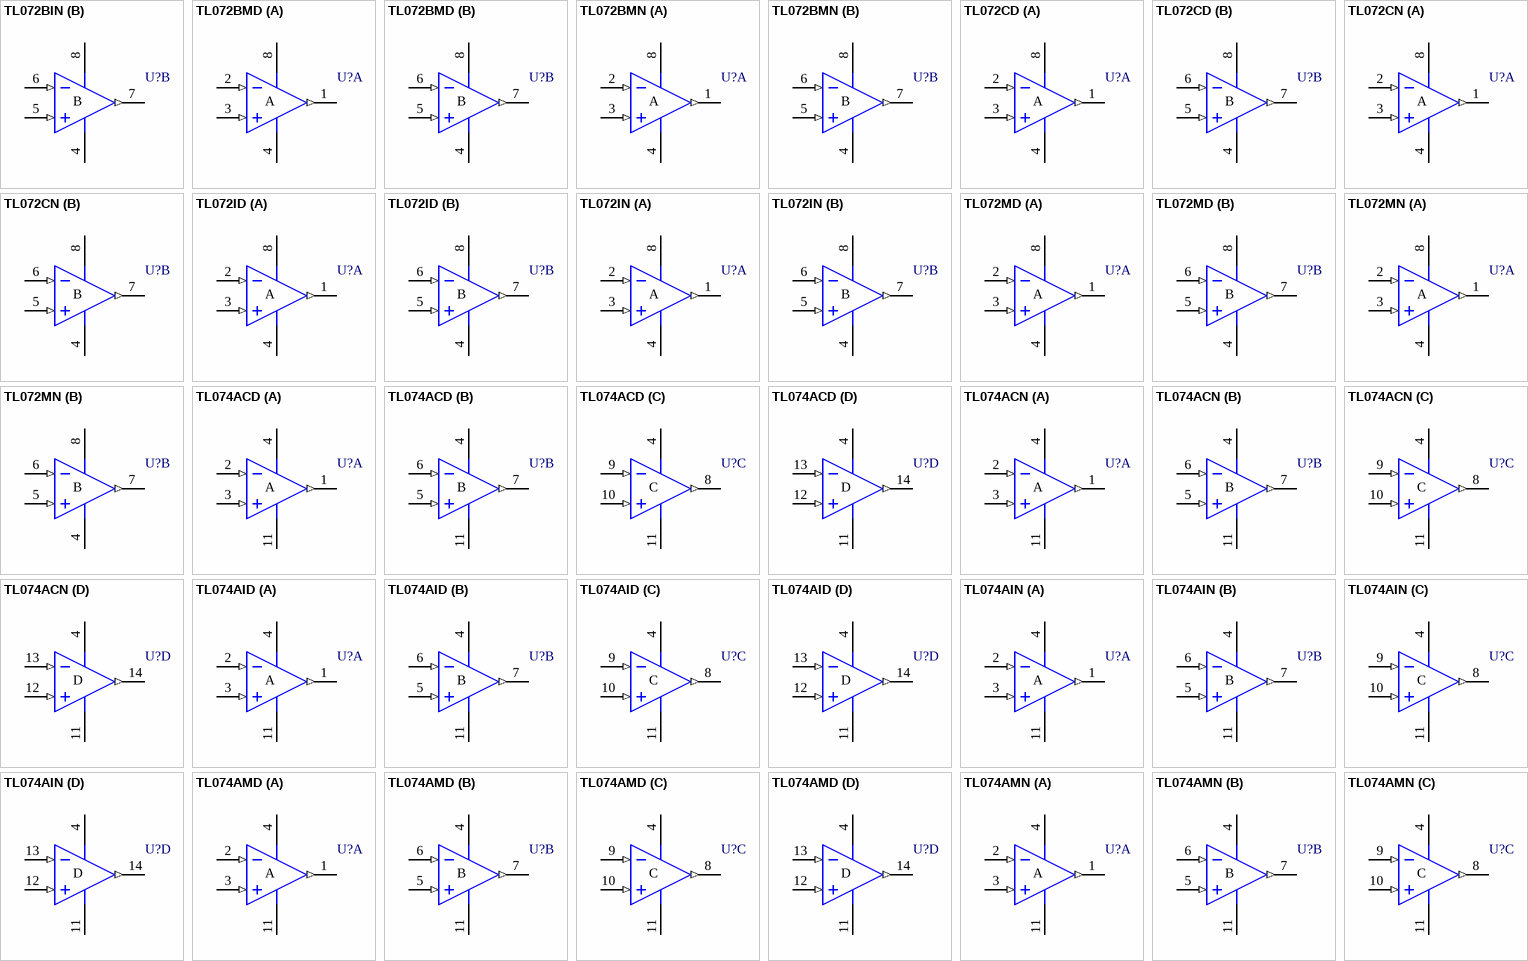
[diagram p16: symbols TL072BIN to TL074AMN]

## TL072BIN
designator U?
Low-Noise J-FET Dual Operational Amplifier
footprint DIP8 (DIP; 8 Leads; Row Spacing 7.62 mm; Pitch 2.54 mm)
3D model DIP8 (DIP; 8 Leads; Row Spacing 7.62 mm; Pitch 2.54 mm)
simulation model TL072 (SUBCKT)
pins on every part: 4 V- (power), 8 V+ (power)
part A pins: 1 OUT (out), 2 IN- (in), 3 IN+ (in)
part B pins: 5 IN+ (in), 6 IN- (in), 7 OUT (out)

## TL072BMD
designator U?
Low-Noise J-FET Dual Operational Amplifier
footprint SO8_N (SOIC, 8-Leads, Body 4.9x3.9mm, Pitch 1.27mm, IPC Medium Density)
footprint SO8_L (SOIC, 8-Leads, Body 4.9x3.9mm, Pitch 1.27mm, IPC High Density)
footprint SO8_M (SOIC, 8-Leads, Body 4.9x3.9mm, Pitch 1.27mm, IPC Low Density)
3D model SO8 (8-Pin Small Outline Integrated Circuit 1.27 mm Pitch)
simulation model TL072 (SUBCKT)
pins on every part: 4 V- (power), 8 V+ (power)
part A pins: 1 OUT (out), 2 IN- (in), 3 IN+ (in)
part B pins: 5 IN+ (in), 6 IN- (in), 7 OUT (out)

## TL072BMN
designator U?
Low-Noise J-FET Dual Operational Amplifier
footprint DIP8 (DIP; 8 Leads; Row Spacing 7.62 mm; Pitch 2.54 mm)
3D model DIP8 (DIP; 8 Leads; Row Spacing 7.62 mm; Pitch 2.54 mm)
simulation model TL072 (SUBCKT)
pins on every part: 4 V- (power), 8 V+ (power)
part A pins: 1 OUT (out), 2 IN- (in), 3 IN+ (in)
part B pins: 5 IN+ (in), 6 IN- (in), 7 OUT (out)

## TL072CD
designator U?
Low-Noise J-FET Dual Operational Amplifier
footprint SO8_N (SOIC, 8-Leads, Body 4.9x3.9mm, Pitch 1.27mm, IPC Medium Density)
footprint SO8_L (SOIC, 8-Leads, Body 4.9x3.9mm, Pitch 1.27mm, IPC High Density)
footprint SO8_M (SOIC, 8-Leads, Body 4.9x3.9mm, Pitch 1.27mm, IPC Low Density)
3D model SO8 (8-Pin Small Outline Integrated Circuit 1.27 mm Pitch)
simulation model TL072 (SUBCKT)
pins on every part: 4 V- (power), 8 V+ (power)
part A pins: 1 OUT (out), 2 IN- (in), 3 IN+ (in)
part B pins: 5 IN+ (in), 6 IN- (in), 7 OUT (out)

## TL072CN
designator U?
Low-Noise J-FET Dual Operational Amplifier
footprint DIP8 (DIP; 8 Leads; Row Spacing 7.62 mm; Pitch 2.54 mm)
3D model DIP8 (DIP; 8 Leads; Row Spacing 7.62 mm; Pitch 2.54 mm)
simulation model TL072 (SUBCKT)
pins on every part: 4 V- (power), 8 V+ (power)
part A pins: 1 OUT (out), 2 IN- (in), 3 IN+ (in)
part B pins: 5 IN+ (in), 6 IN- (in), 7 OUT (out)

## TL072ID
designator U?
Low-Noise J-FET Dual Operational Amplifier
footprint SO8_N (SOIC, 8-Leads, Body 4.9x3.9mm, Pitch 1.27mm, IPC Medium Density)
footprint SO8_L (SOIC, 8-Leads, Body 4.9x3.9mm, Pitch 1.27mm, IPC High Density)
footprint SO8_M (SOIC, 8-Leads, Body 4.9x3.9mm, Pitch 1.27mm, IPC Low Density)
3D model SO8 (8-Pin Small Outline Integrated Circuit 1.27 mm Pitch)
simulation model TL072 (SUBCKT)
pins on every part: 4 V- (power), 8 V+ (power)
part A pins: 1 OUT (out), 2 IN- (in), 3 IN+ (in)
part B pins: 5 IN+ (in), 6 IN- (in), 7 OUT (out)

## TL072IN
designator U?
Low-Noise J-FET Dual Operational Amplifier
footprint DIP8 (DIP; 8 Leads; Row Spacing 7.62 mm; Pitch 2.54 mm)
3D model DIP8 (DIP; 8 Leads; Row Spacing 7.62 mm; Pitch 2.54 mm)
simulation model TL072 (SUBCKT)
pins on every part: 4 V- (power), 8 V+ (power)
part A pins: 1 OUT (out), 2 IN- (in), 3 IN+ (in)
part B pins: 5 IN+ (in), 6 IN- (in), 7 OUT (out)

## TL072MD
designator U?
Low-Noise J-FET Dual Operational Amplifier
footprint SO8_N (SOIC, 8-Leads, Body 4.9x3.9mm, Pitch 1.27mm, IPC Medium Density)
footprint SO8_L (SOIC, 8-Leads, Body 4.9x3.9mm, Pitch 1.27mm, IPC High Density)
footprint SO8_M (SOIC, 8-Leads, Body 4.9x3.9mm, Pitch 1.27mm, IPC Low Density)
3D model SO8 (8-Pin Small Outline Integrated Circuit 1.27 mm Pitch)
simulation model TL072 (SUBCKT)
pins on every part: 4 V- (power), 8 V+ (power)
part A pins: 1 OUT (out), 2 IN- (in), 3 IN+ (in)
part B pins: 5 IN+ (in), 6 IN- (in), 7 OUT (out)

## TL072MN
designator U?
Low-Noise J-FET Dual Operational Amplifier
footprint DIP8 (DIP; 8 Leads; Row Spacing 7.62 mm; Pitch 2.54 mm)
3D model DIP8 (DIP; 8 Leads; Row Spacing 7.62 mm; Pitch 2.54 mm)
simulation model TL072 (SUBCKT)
pins on every part: 4 V- (power), 8 V+ (power)
part A pins: 1 OUT (out), 2 IN- (in), 3 IN+ (in)
part B pins: 5 IN+ (in), 6 IN- (in), 7 OUT (out)

## TL074ACD
designator U?
Low-Noise J-FET Quad Operational Amplifier
footprint SO14_N (SOIC, 14-Leads, Body 8.7x3.9mm, Pitch 1.27mm, IPC Medium Density)
footprint SO14_L (SOIC, 14-Leads, Body 8.7x3.9mm, Pitch 1.27mm, IPC High Density)
footprint SO14_M (SOIC, 14-Leads, Body 8.7x3.9mm, Pitch 1.27mm, IPC Low Density)
3D model SO14 (14-Pin Small Outline Integrated Circuit 1.27 mm Pitch)
simulation model TL074 (SUBCKT)
pins on every part: 4 V+ (power), 11 V- (power)
part A pins: 1 OUT (out), 2 IN- (in), 3 IN+ (in)
part B pins: 5 IN+ (in), 6 IN- (in), 7 OUT (out)
part C pins: 8 OUT (out), 9 IN- (in), 10 IN+ (in)
part D pins: 12 IN+ (in), 13 IN- (in), 14 OUT (out)

## TL074ACN
designator U?
Low-Noise J-FET Quad Operational Amplifier
footprint DIP14 (DIP; 14 Leads; Row Spacing 7.62 mm; Pitch 2.54 mm)
3D model DIP14 (DIP; 14 Leads; Row Spacing 7.62 mm; Pitch 2.54 mm)
simulation model TL074 (SUBCKT)
pins on every part: 4 V+ (power), 11 V- (power)
part A pins: 1 OUT (out), 2 IN- (in), 3 IN+ (in)
part B pins: 5 IN+ (in), 6 IN- (in), 7 OUT (out)
part C pins: 8 OUT (out), 9 IN- (in), 10 IN+ (in)
part D pins: 12 IN+ (in), 13 IN- (in), 14 OUT (out)

## TL074AID
designator U?
Low-Noise J-FET Quad Operational Amplifier
footprint SO14_N (SOIC, 14-Leads, Body 8.7x3.9mm, Pitch 1.27mm, IPC Medium Density)
footprint SO14_L (SOIC, 14-Leads, Body 8.7x3.9mm, Pitch 1.27mm, IPC High Density)
footprint SO14_M (SOIC, 14-Leads, Body 8.7x3.9mm, Pitch 1.27mm, IPC Low Density)
3D model SO14 (14-Pin Small Outline Integrated Circuit 1.27 mm Pitch)
simulation model TL074 (SUBCKT)
pins on every part: 4 V+ (power), 11 V- (power)
part A pins: 1 OUT (out), 2 IN- (in), 3 IN+ (in)
part B pins: 5 IN+ (in), 6 IN- (in), 7 OUT (out)
part C pins: 8 OUT (out), 9 IN- (in), 10 IN+ (in)
part D pins: 12 IN+ (in), 13 IN- (in), 14 OUT (out)

## TL074AIN
designator U?
Low-Noise J-FET Quad Operational Amplifier
footprint DIP14 (DIP; 14 Leads; Row Spacing 7.62 mm; Pitch 2.54 mm)
3D model DIP14 (DIP; 14 Leads; Row Spacing 7.62 mm; Pitch 2.54 mm)
simulation model TL074 (SUBCKT)
pins on every part: 4 V+ (power), 11 V- (power)
part A pins: 1 OUT (out), 2 IN- (in), 3 IN+ (in)
part B pins: 5 IN+ (in), 6 IN- (in), 7 OUT (out)
part C pins: 8 OUT (out), 9 IN- (in), 10 IN+ (in)
part D pins: 12 IN+ (in), 13 IN- (in), 14 OUT (out)

## TL074AMD
designator U?
Low-Noise J-FET Quad Operational Amplifier
footprint SO14_N (SOIC, 14-Leads, Body 8.7x3.9mm, Pitch 1.27mm, IPC Medium Density)
footprint SO14_L (SOIC, 14-Leads, Body 8.7x3.9mm, Pitch 1.27mm, IPC High Density)
footprint SO14_M (SOIC, 14-Leads, Body 8.7x3.9mm, Pitch 1.27mm, IPC Low Density)
3D model SO14 (14-Pin Small Outline Integrated Circuit 1.27 mm Pitch)
simulation model TL074 (SUBCKT)
pins on every part: 4 V+ (power), 11 V- (power)
part A pins: 1 OUT (out), 2 IN- (in), 3 IN+ (in)
part B pins: 5 IN+ (in), 6 IN- (in), 7 OUT (out)
part C pins: 8 OUT (out), 9 IN- (in), 10 IN+ (in)
part D pins: 12 IN+ (in), 13 IN- (in), 14 OUT (out)

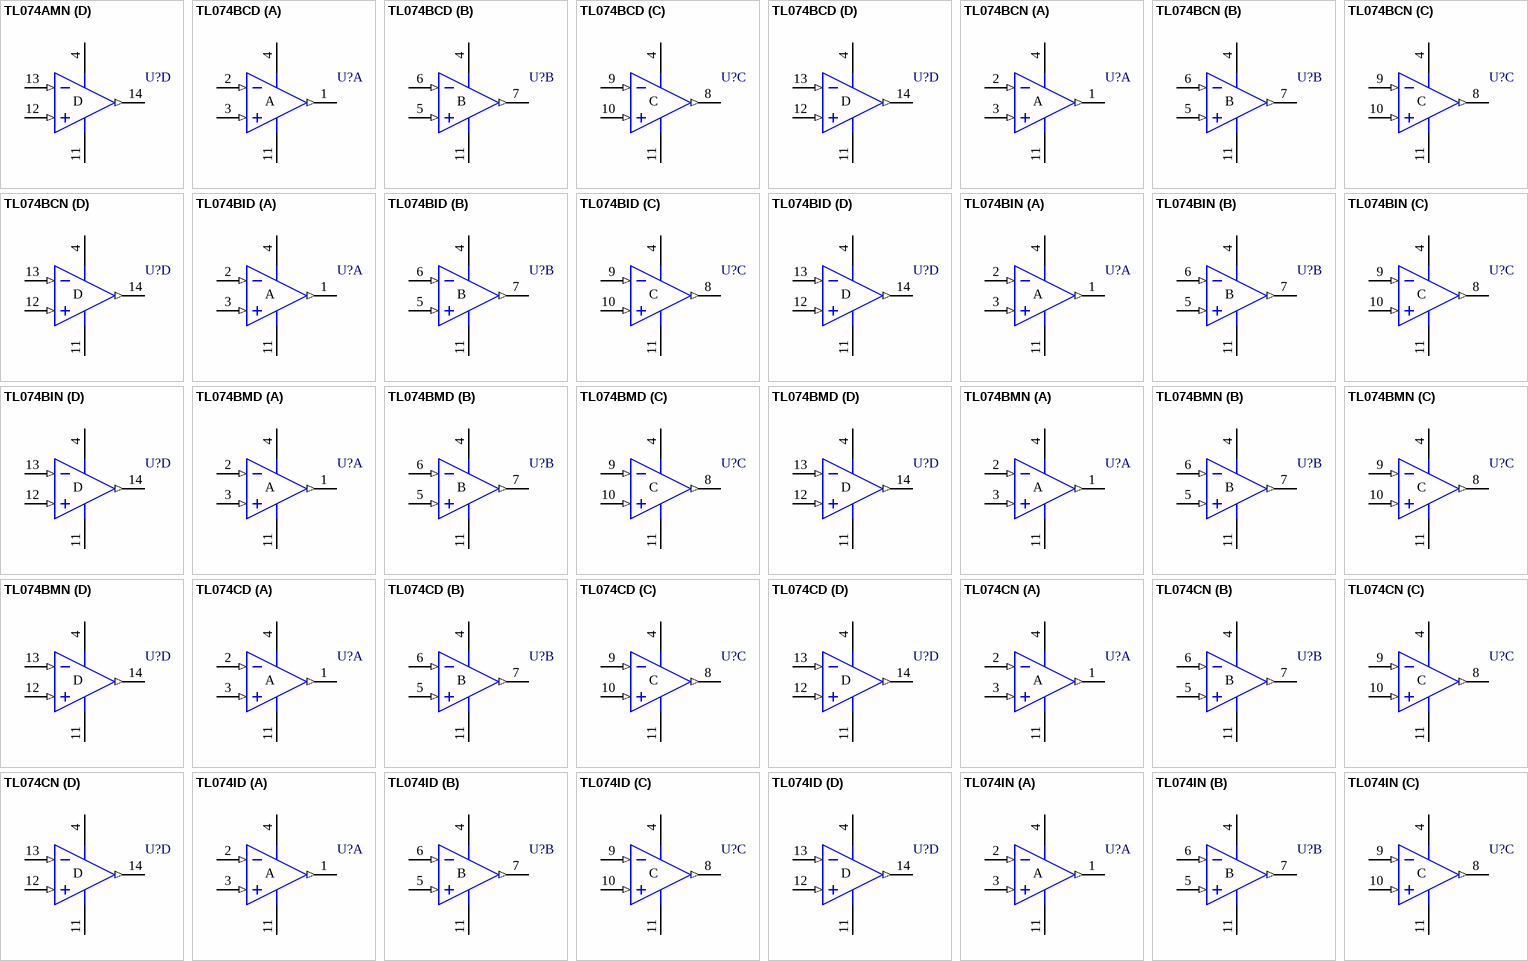
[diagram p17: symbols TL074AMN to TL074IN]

## TL074AMN
designator U?
Low-Noise J-FET Quad Operational Amplifier
footprint DIP14 (DIP; 14 Leads; Row Spacing 7.62 mm; Pitch 2.54 mm)
3D model DIP14 (DIP; 14 Leads; Row Spacing 7.62 mm; Pitch 2.54 mm)
simulation model TL074 (SUBCKT)
pins on every part: 4 V+ (power), 11 V- (power)
part A pins: 1 OUT (out), 2 IN- (in), 3 IN+ (in)
part B pins: 5 IN+ (in), 6 IN- (in), 7 OUT (out)
part C pins: 8 OUT (out), 9 IN- (in), 10 IN+ (in)
part D pins: 12 IN+ (in), 13 IN- (in), 14 OUT (out)

## TL074BCD
designator U?
Low-Noise J-FET Quad Operational Amplifier
footprint SO14_N (SOIC, 14-Leads, Body 8.7x3.9mm, Pitch 1.27mm, IPC Medium Density)
footprint SO14_L (SOIC, 14-Leads, Body 8.7x3.9mm, Pitch 1.27mm, IPC High Density)
footprint SO14_M (SOIC, 14-Leads, Body 8.7x3.9mm, Pitch 1.27mm, IPC Low Density)
3D model SO14 (14-Pin Small Outline Integrated Circuit 1.27 mm Pitch)
simulation model TL074 (SUBCKT)
pins on every part: 4 V+ (power), 11 V- (power)
part A pins: 1 OUT (out), 2 IN- (in), 3 IN+ (in)
part B pins: 5 IN+ (in), 6 IN- (in), 7 OUT (out)
part C pins: 8 OUT (out), 9 IN- (in), 10 IN+ (in)
part D pins: 12 IN+ (in), 13 IN- (in), 14 OUT (out)

## TL074BCN
designator U?
Low-Noise J-FET Quad Operational Amplifier
footprint DIP14 (DIP; 14 Leads; Row Spacing 7.62 mm; Pitch 2.54 mm)
3D model DIP14 (DIP; 14 Leads; Row Spacing 7.62 mm; Pitch 2.54 mm)
simulation model TL074 (SUBCKT)
pins on every part: 4 V+ (power), 11 V- (power)
part A pins: 1 OUT (out), 2 IN- (in), 3 IN+ (in)
part B pins: 5 IN+ (in), 6 IN- (in), 7 OUT (out)
part C pins: 8 OUT (out), 9 IN- (in), 10 IN+ (in)
part D pins: 12 IN+ (in), 13 IN- (in), 14 OUT (out)

## TL074BID
designator U?
Low-Noise J-FET Quad Operational Amplifier
footprint SO14_N (SOIC, 14-Leads, Body 8.7x3.9mm, Pitch 1.27mm, IPC Medium Density)
footprint SO14_L (SOIC, 14-Leads, Body 8.7x3.9mm, Pitch 1.27mm, IPC High Density)
footprint SO14_M (SOIC, 14-Leads, Body 8.7x3.9mm, Pitch 1.27mm, IPC Low Density)
3D model SO14 (14-Pin Small Outline Integrated Circuit 1.27 mm Pitch)
simulation model TL074 (SUBCKT)
pins on every part: 4 V+ (power), 11 V- (power)
part A pins: 1 OUT (out), 2 IN- (in), 3 IN+ (in)
part B pins: 5 IN+ (in), 6 IN- (in), 7 OUT (out)
part C pins: 8 OUT (out), 9 IN- (in), 10 IN+ (in)
part D pins: 12 IN+ (in), 13 IN- (in), 14 OUT (out)

## TL074BIN
designator U?
Low-Noise J-FET Quad Operational Amplifier
footprint DIP14 (DIP; 14 Leads; Row Spacing 7.62 mm; Pitch 2.54 mm)
3D model DIP14 (DIP; 14 Leads; Row Spacing 7.62 mm; Pitch 2.54 mm)
simulation model TL074 (SUBCKT)
pins on every part: 4 V+ (power), 11 V- (power)
part A pins: 1 OUT (out), 2 IN- (in), 3 IN+ (in)
part B pins: 5 IN+ (in), 6 IN- (in), 7 OUT (out)
part C pins: 8 OUT (out), 9 IN- (in), 10 IN+ (in)
part D pins: 12 IN+ (in), 13 IN- (in), 14 OUT (out)

## TL074BMD
designator U?
Low-Noise J-FET Quad Operational Amplifier
footprint SO14_N (SOIC, 14-Leads, Body 8.7x3.9mm, Pitch 1.27mm, IPC Medium Density)
footprint SO14_L (SOIC, 14-Leads, Body 8.7x3.9mm, Pitch 1.27mm, IPC High Density)
footprint SO14_M (SOIC, 14-Leads, Body 8.7x3.9mm, Pitch 1.27mm, IPC Low Density)
3D model SO14 (14-Pin Small Outline Integrated Circuit 1.27 mm Pitch)
simulation model TL074 (SUBCKT)
pins on every part: 4 V+ (power), 11 V- (power)
part A pins: 1 OUT (out), 2 IN- (in), 3 IN+ (in)
part B pins: 5 IN+ (in), 6 IN- (in), 7 OUT (out)
part C pins: 8 OUT (out), 9 IN- (in), 10 IN+ (in)
part D pins: 12 IN+ (in), 13 IN- (in), 14 OUT (out)

## TL074BMN
designator U?
Low-Noise J-FET Quad Operational Amplifier
footprint DIP14 (DIP; 14 Leads; Row Spacing 7.62 mm; Pitch 2.54 mm)
3D model DIP14 (DIP; 14 Leads; Row Spacing 7.62 mm; Pitch 2.54 mm)
simulation model TL074 (SUBCKT)
pins on every part: 4 V+ (power), 11 V- (power)
part A pins: 1 OUT (out), 2 IN- (in), 3 IN+ (in)
part B pins: 5 IN+ (in), 6 IN- (in), 7 OUT (out)
part C pins: 8 OUT (out), 9 IN- (in), 10 IN+ (in)
part D pins: 12 IN+ (in), 13 IN- (in), 14 OUT (out)

## TL074CD
designator U?
Low-Noise J-FET Quad Operational Amplifier
footprint SO14_N (SOIC, 14-Leads, Body 8.7x3.9mm, Pitch 1.27mm, IPC Medium Density)
footprint SO14_L (SOIC, 14-Leads, Body 8.7x3.9mm, Pitch 1.27mm, IPC High Density)
footprint SO14_M (SOIC, 14-Leads, Body 8.7x3.9mm, Pitch 1.27mm, IPC Low Density)
3D model SO14 (14-Pin Small Outline Integrated Circuit 1.27 mm Pitch)
simulation model TL074 (SUBCKT)
pins on every part: 4 V+ (power), 11 V- (power)
part A pins: 1 OUT (out), 2 IN- (in), 3 IN+ (in)
part B pins: 5 IN+ (in), 6 IN- (in), 7 OUT (out)
part C pins: 8 OUT (out), 9 IN- (in), 10 IN+ (in)
part D pins: 12 IN+ (in), 13 IN- (in), 14 OUT (out)

## TL074CN
designator U?
Low-Noise J-FET Quad Operational Amplifier
footprint DIP14 (DIP; 14 Leads; Row Spacing 7.62 mm; Pitch 2.54 mm)
3D model DIP14 (DIP; 14 Leads; Row Spacing 7.62 mm; Pitch 2.54 mm)
simulation model TL074 (SUBCKT)
pins on every part: 4 V+ (power), 11 V- (power)
part A pins: 1 OUT (out), 2 IN- (in), 3 IN+ (in)
part B pins: 5 IN+ (in), 6 IN- (in), 7 OUT (out)
part C pins: 8 OUT (out), 9 IN- (in), 10 IN+ (in)
part D pins: 12 IN+ (in), 13 IN- (in), 14 OUT (out)

## TL074ID
designator U?
Low-Noise J-FET Quad Operational Amplifier
footprint SO14_N (SOIC, 14-Leads, Body 8.7x3.9mm, Pitch 1.27mm, IPC Medium Density)
footprint SO14_L (SOIC, 14-Leads, Body 8.7x3.9mm, Pitch 1.27mm, IPC High Density)
footprint SO14_M (SOIC, 14-Leads, Body 8.7x3.9mm, Pitch 1.27mm, IPC Low Density)
3D model SO14 (14-Pin Small Outline Integrated Circuit 1.27 mm Pitch)
simulation model TL074 (SUBCKT)
pins on every part: 4 V+ (power), 11 V- (power)
part A pins: 1 OUT (out), 2 IN- (in), 3 IN+ (in)
part B pins: 5 IN+ (in), 6 IN- (in), 7 OUT (out)
part C pins: 8 OUT (out), 9 IN- (in), 10 IN+ (in)
part D pins: 12 IN+ (in), 13 IN- (in), 14 OUT (out)

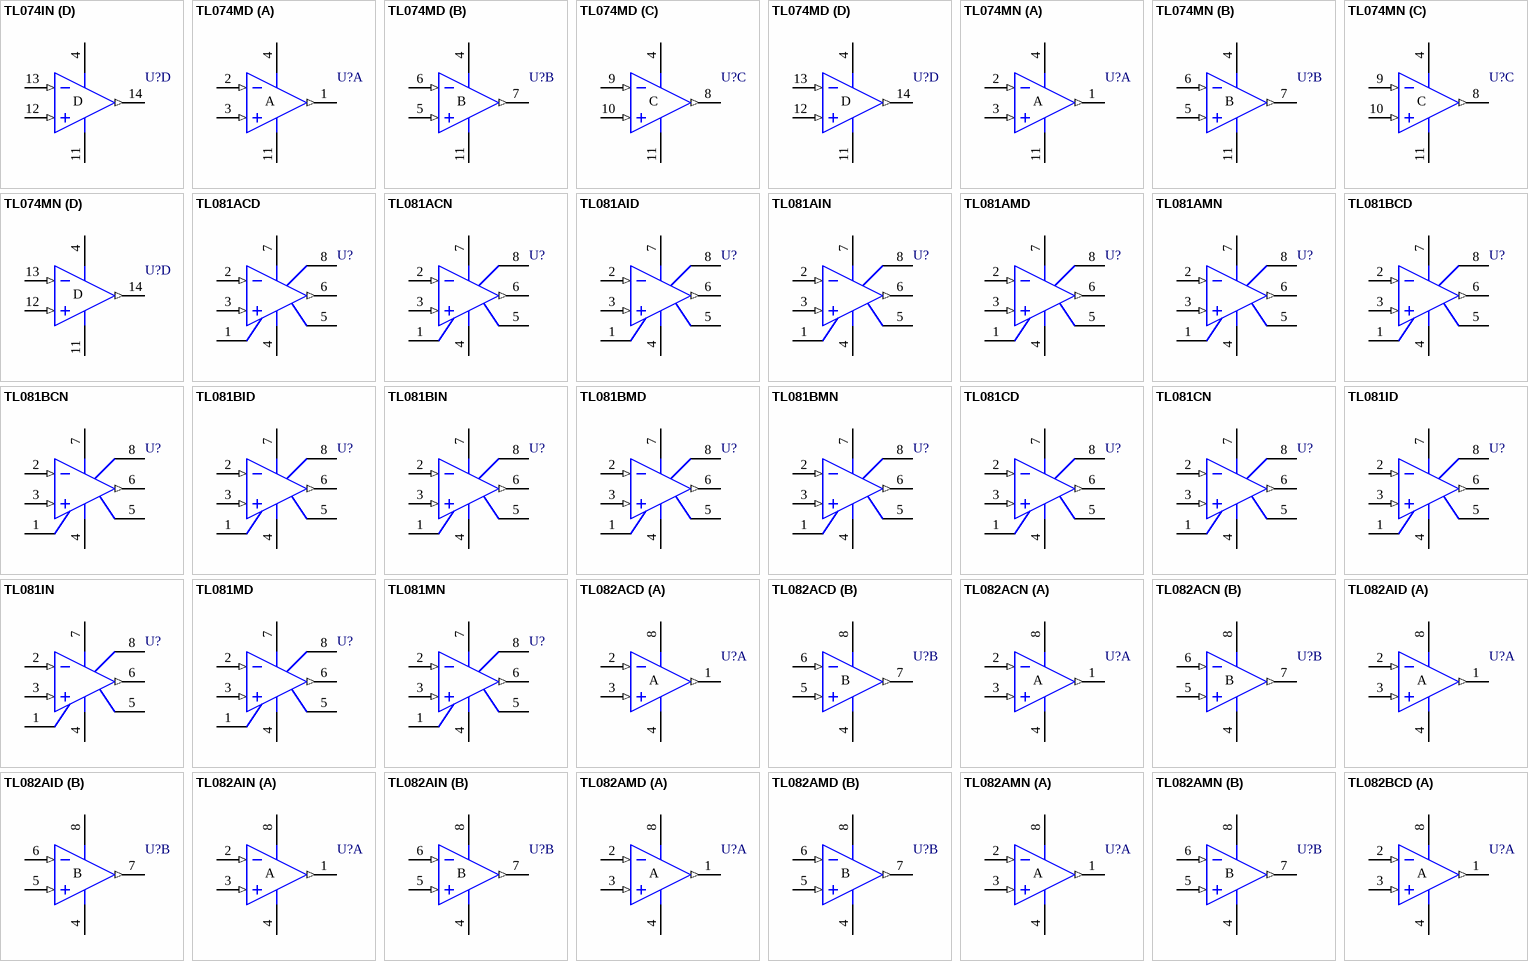
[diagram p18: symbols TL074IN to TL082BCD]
